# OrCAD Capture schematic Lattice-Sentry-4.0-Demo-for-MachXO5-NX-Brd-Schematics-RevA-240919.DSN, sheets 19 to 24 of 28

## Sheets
19 LCMXO3D BANK2_3_4_5: size B
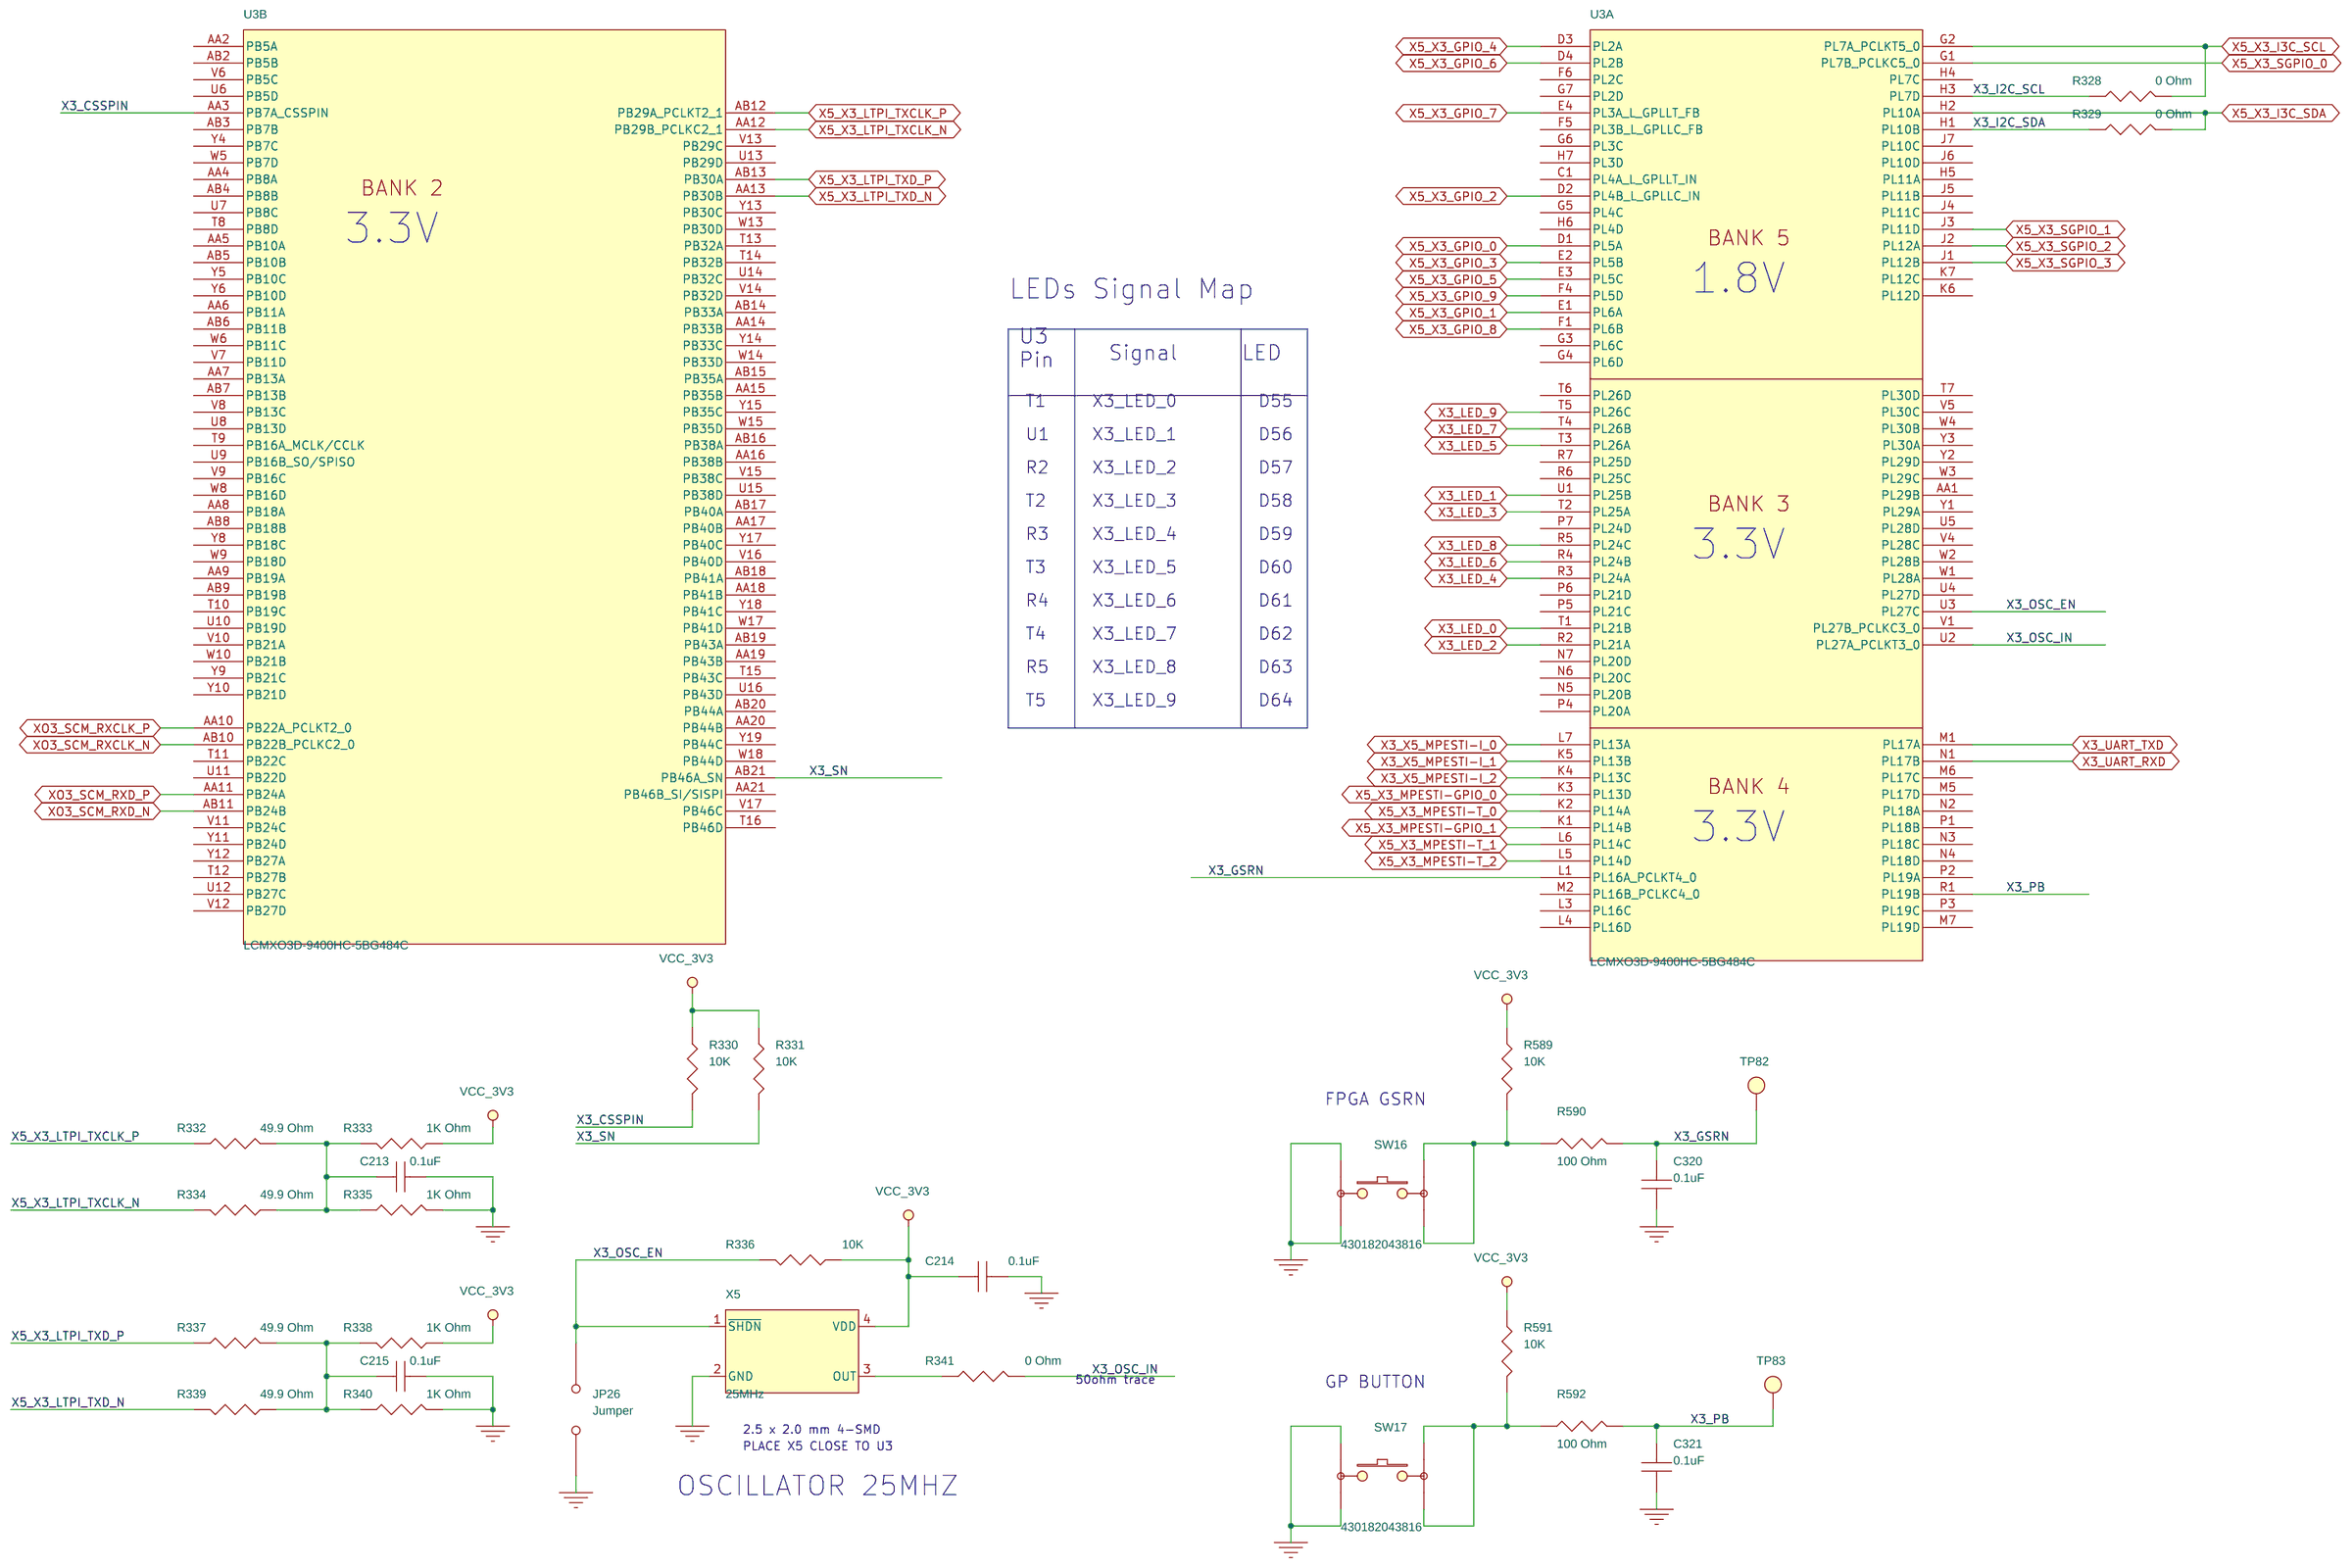
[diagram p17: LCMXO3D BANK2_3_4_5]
20 LCMXO3D POWER: size B
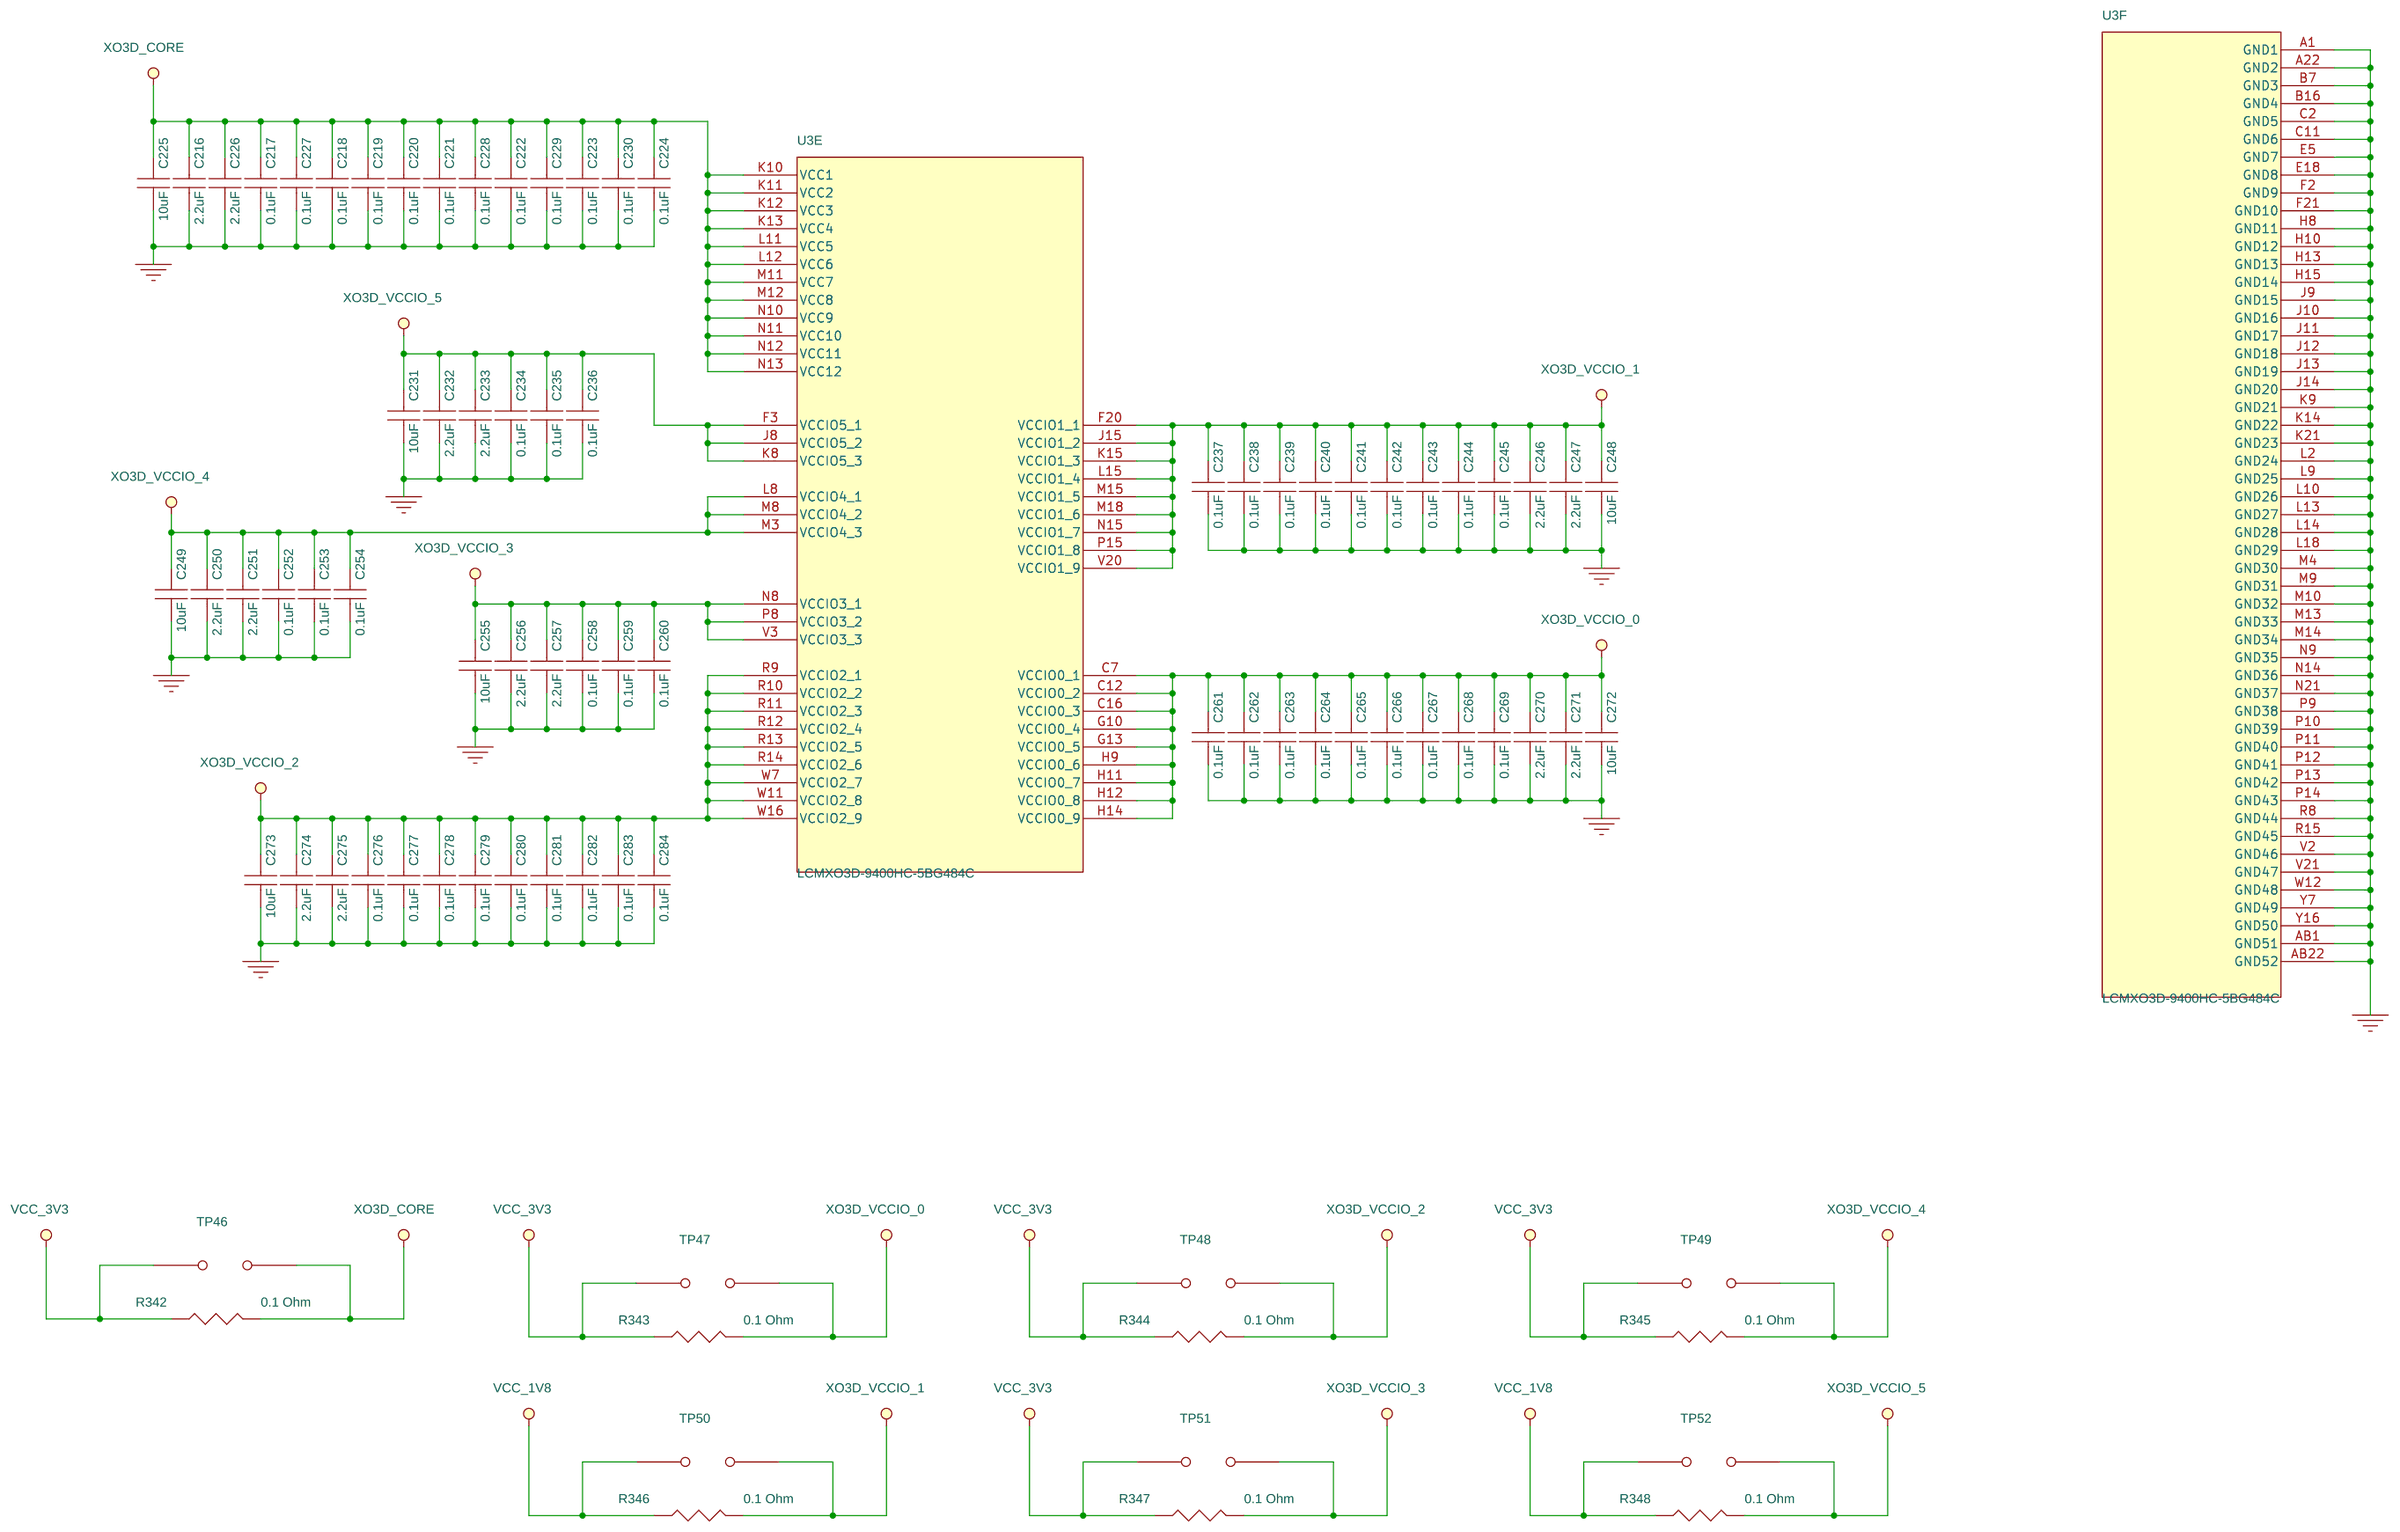
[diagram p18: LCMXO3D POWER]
21 MPESTI: size B
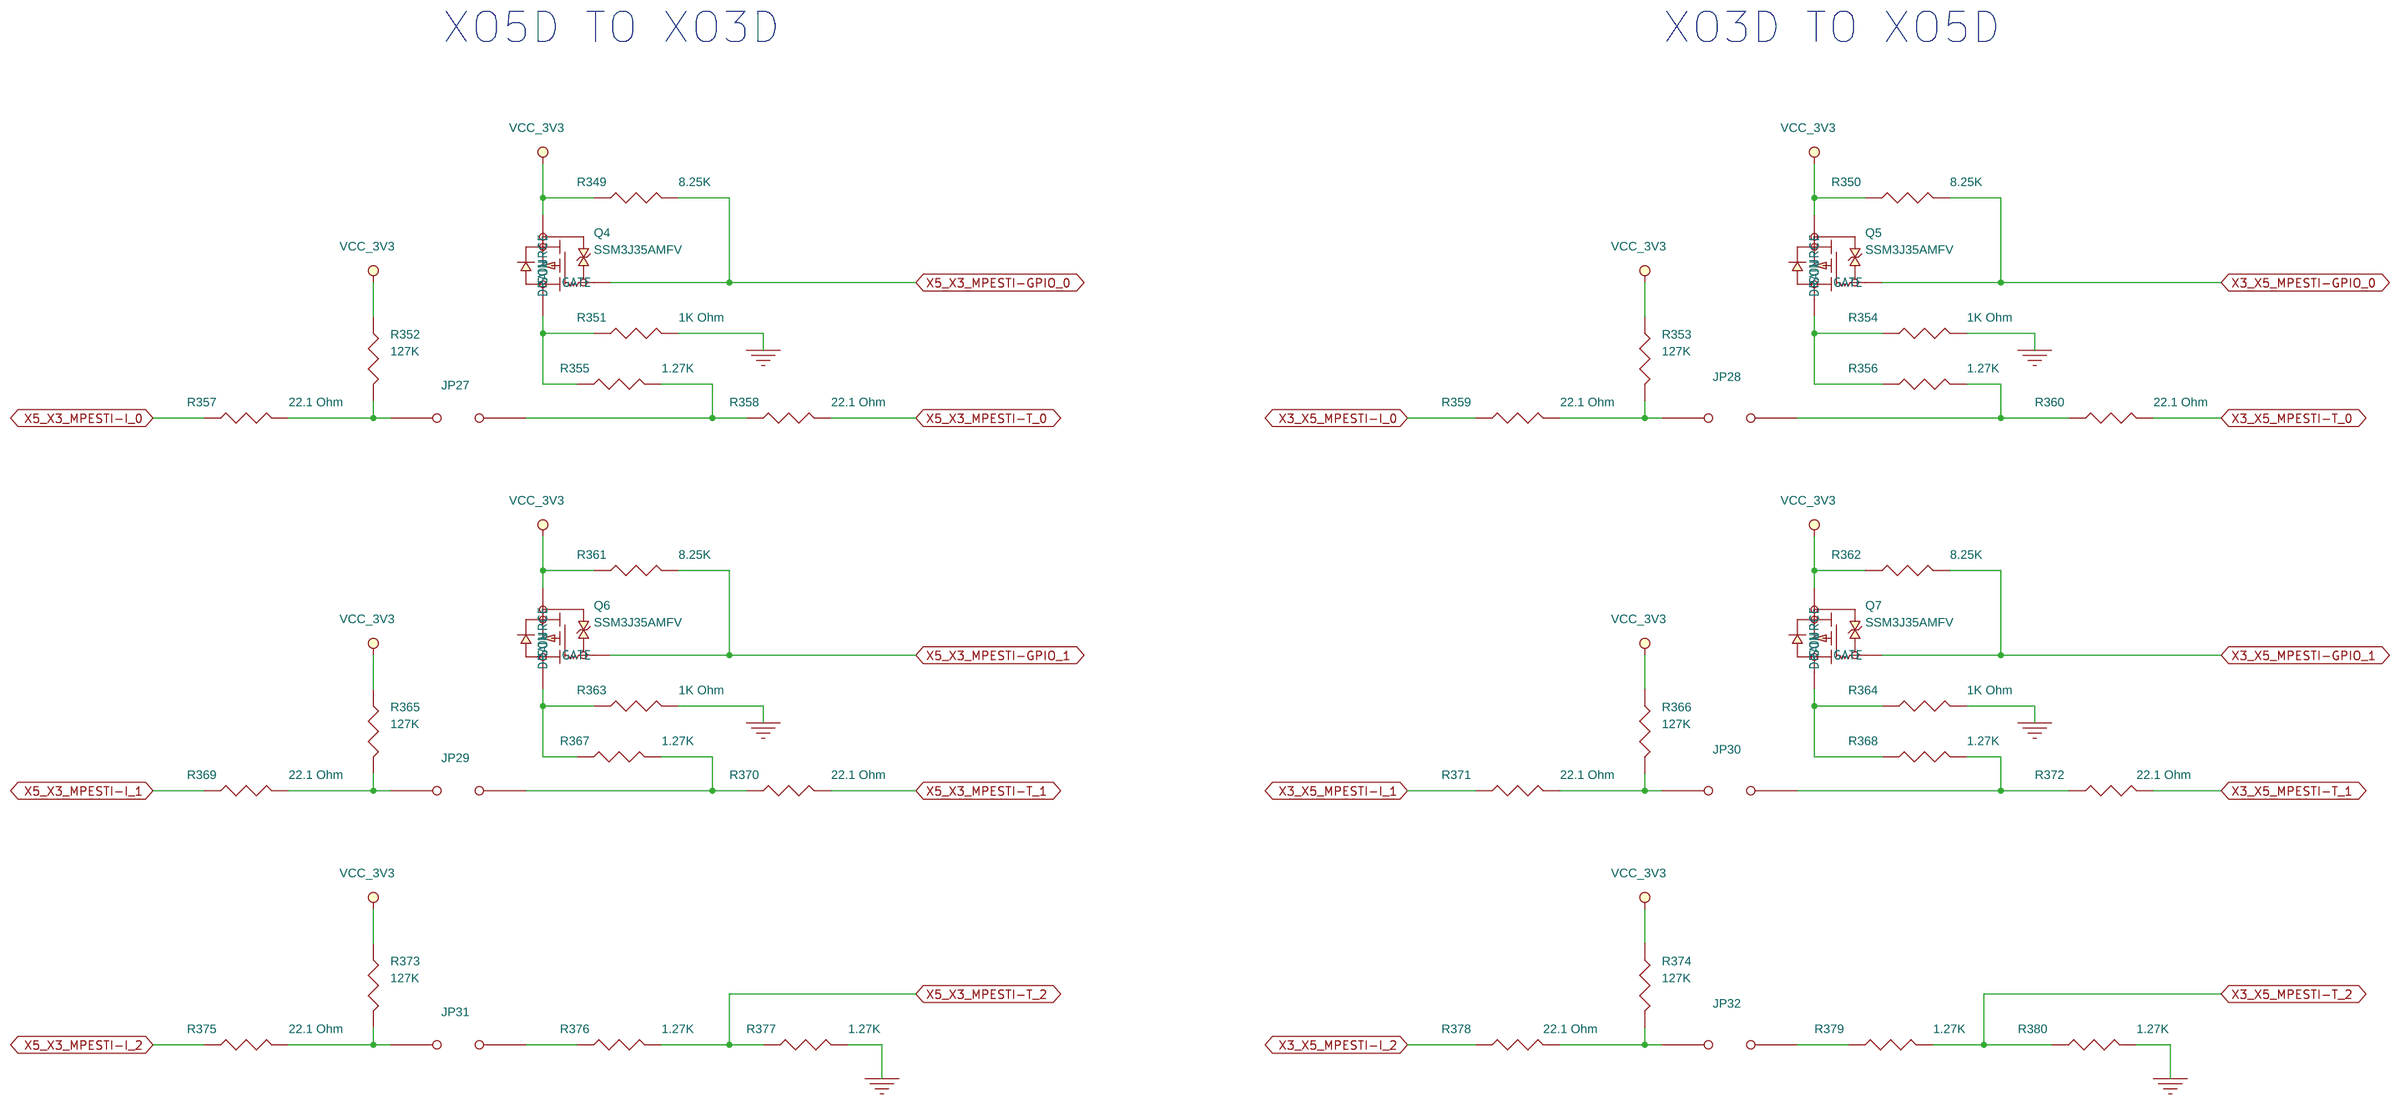
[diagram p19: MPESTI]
22 BMC Flash: size B
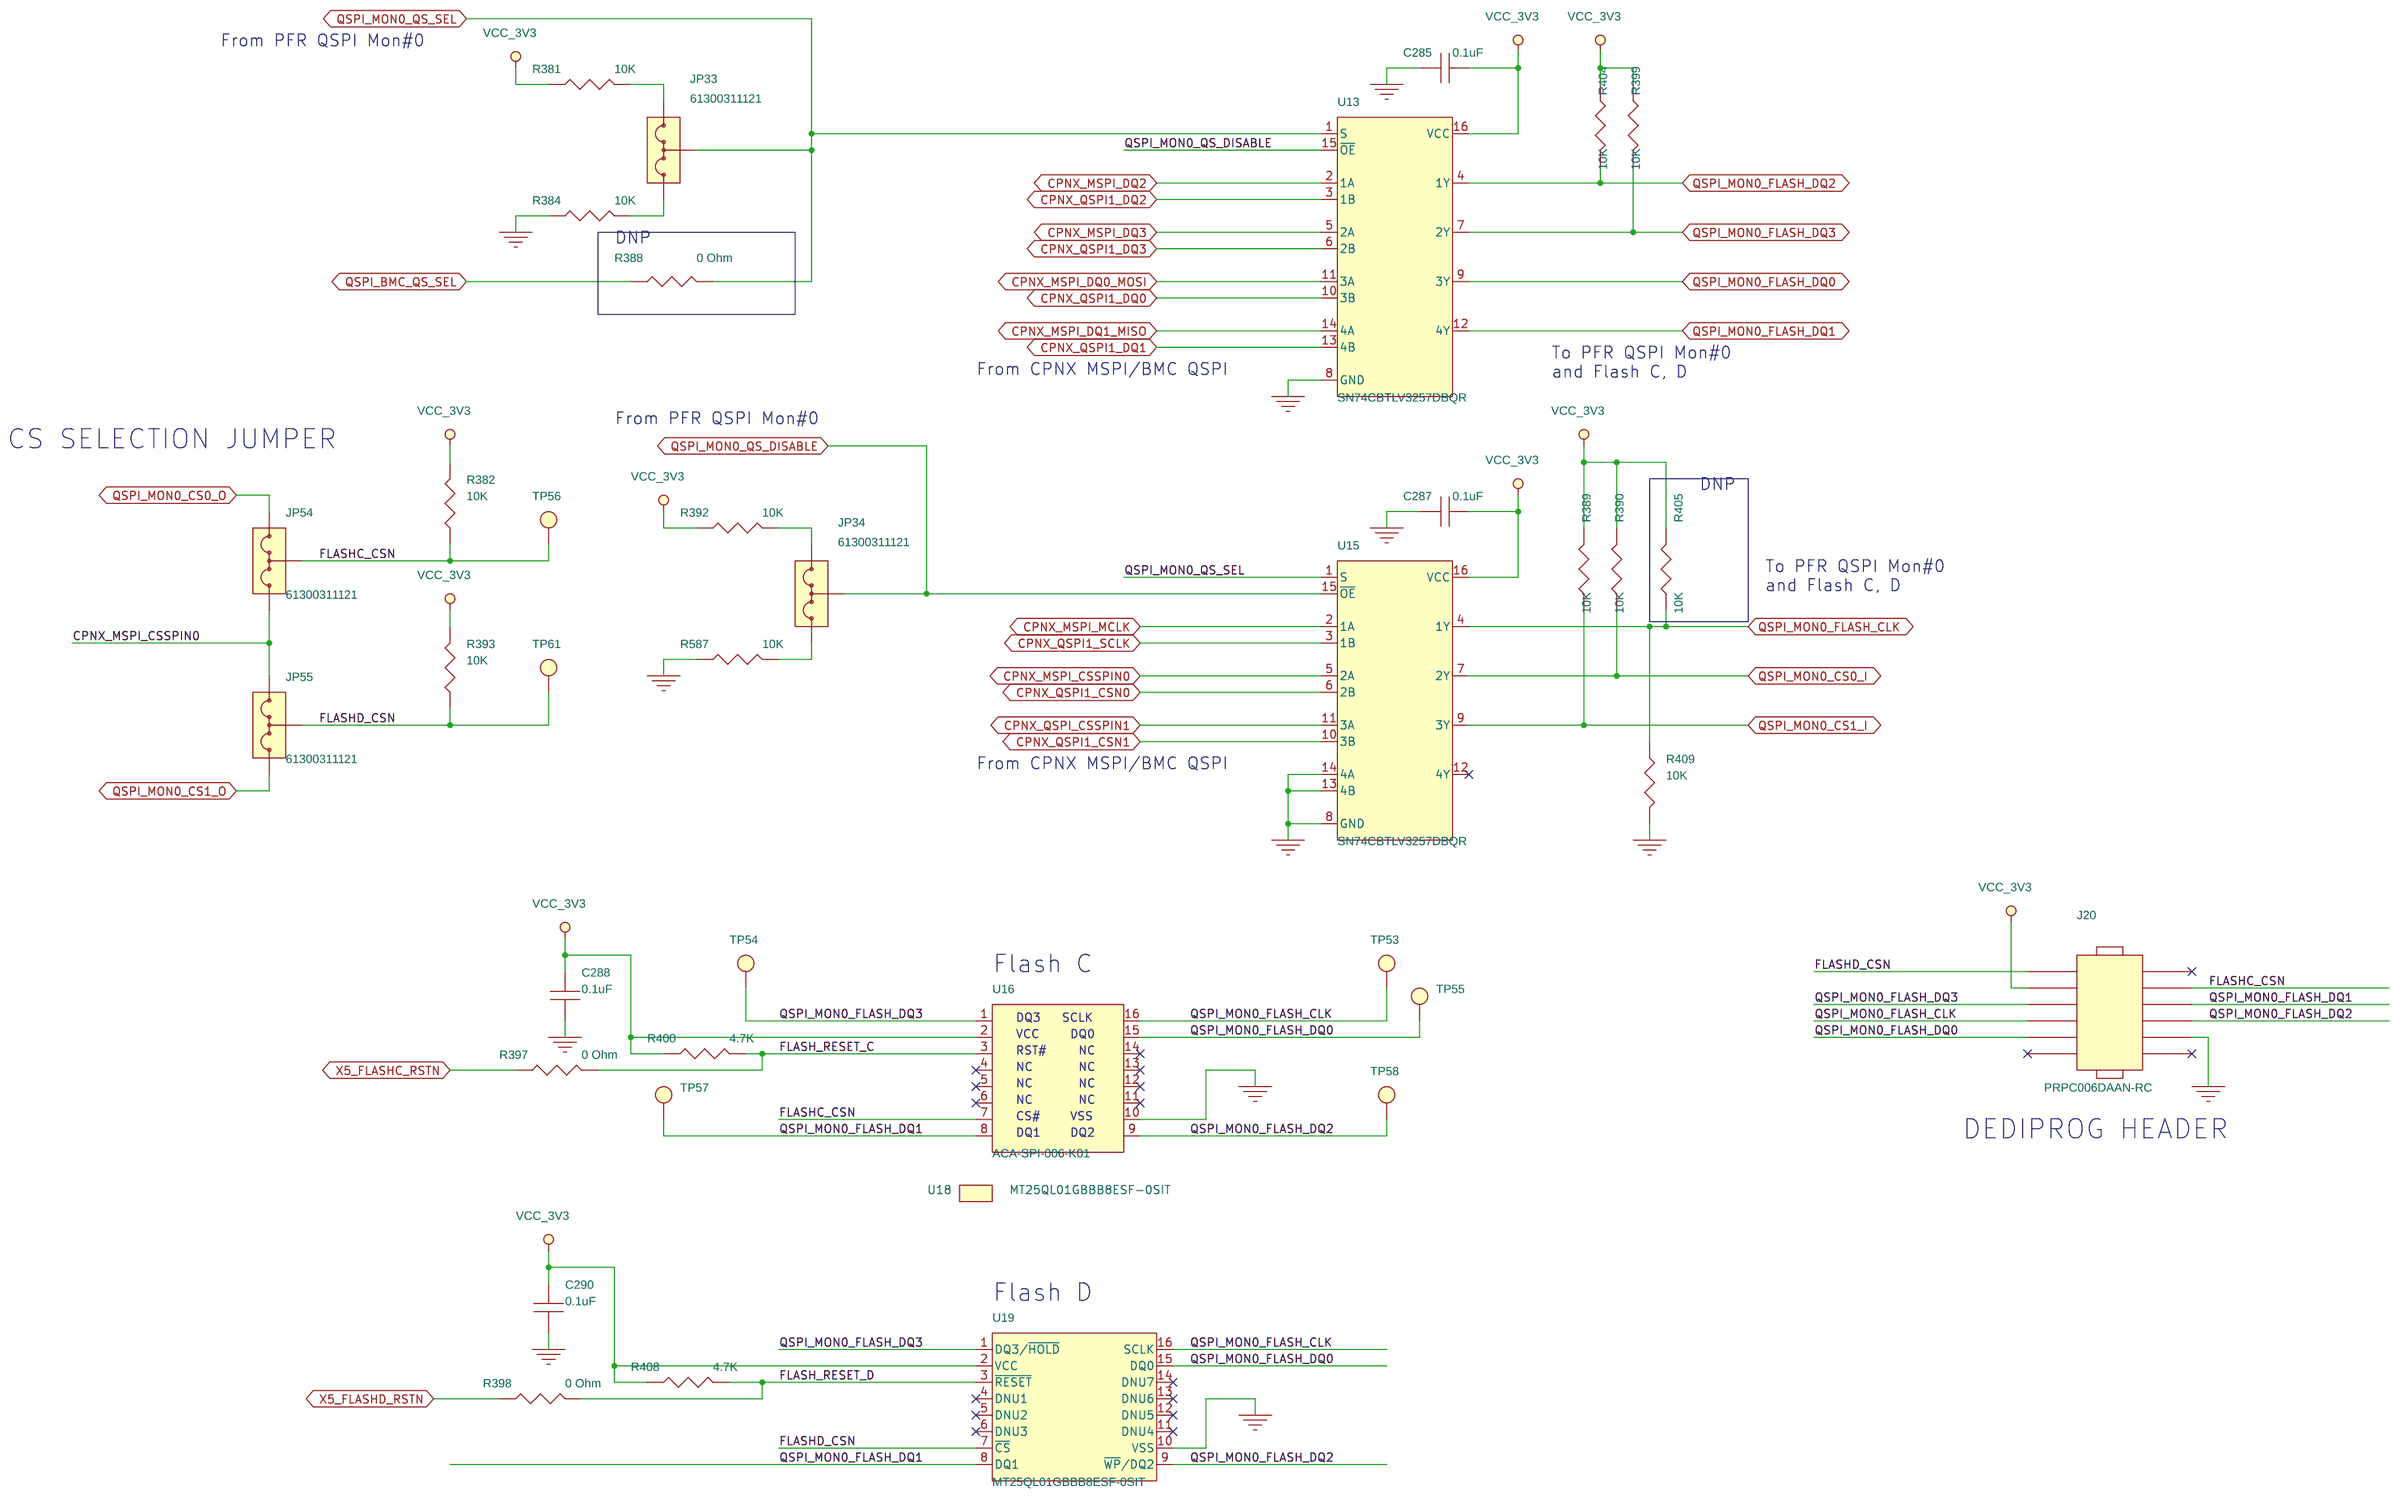
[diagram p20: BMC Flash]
23 PCH Flash: size B
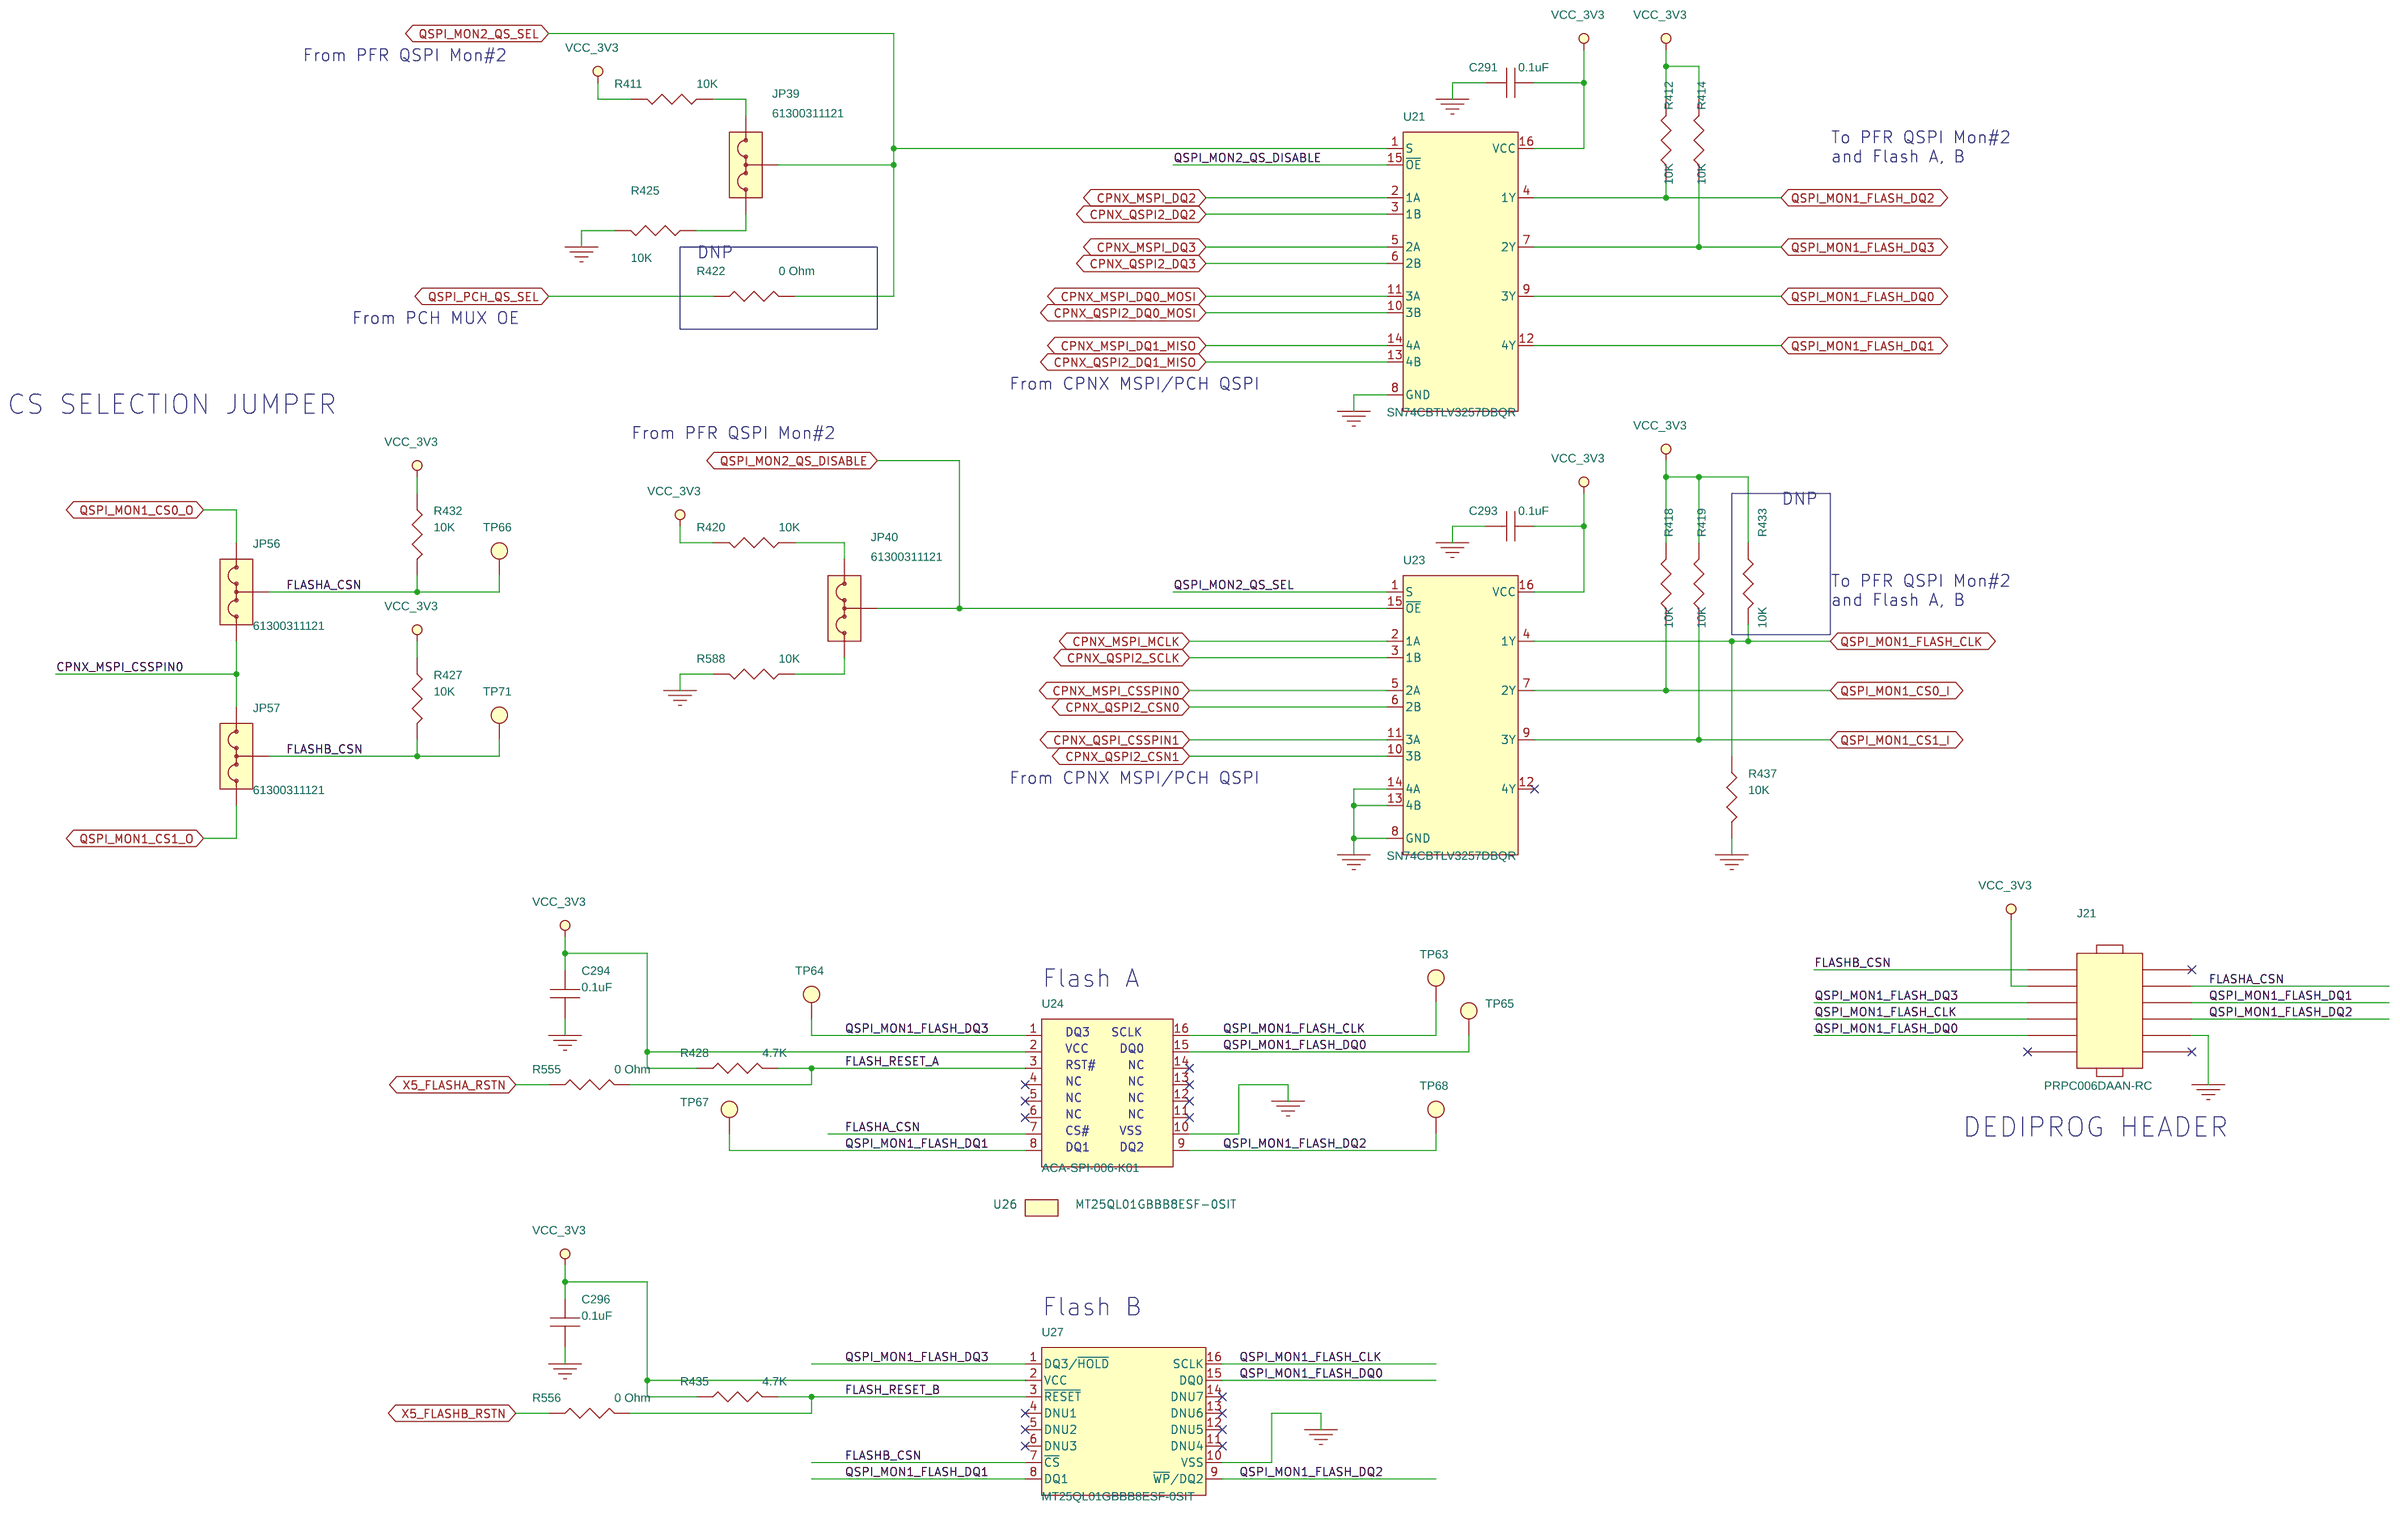
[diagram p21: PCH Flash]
24 JTAG Chain: size B
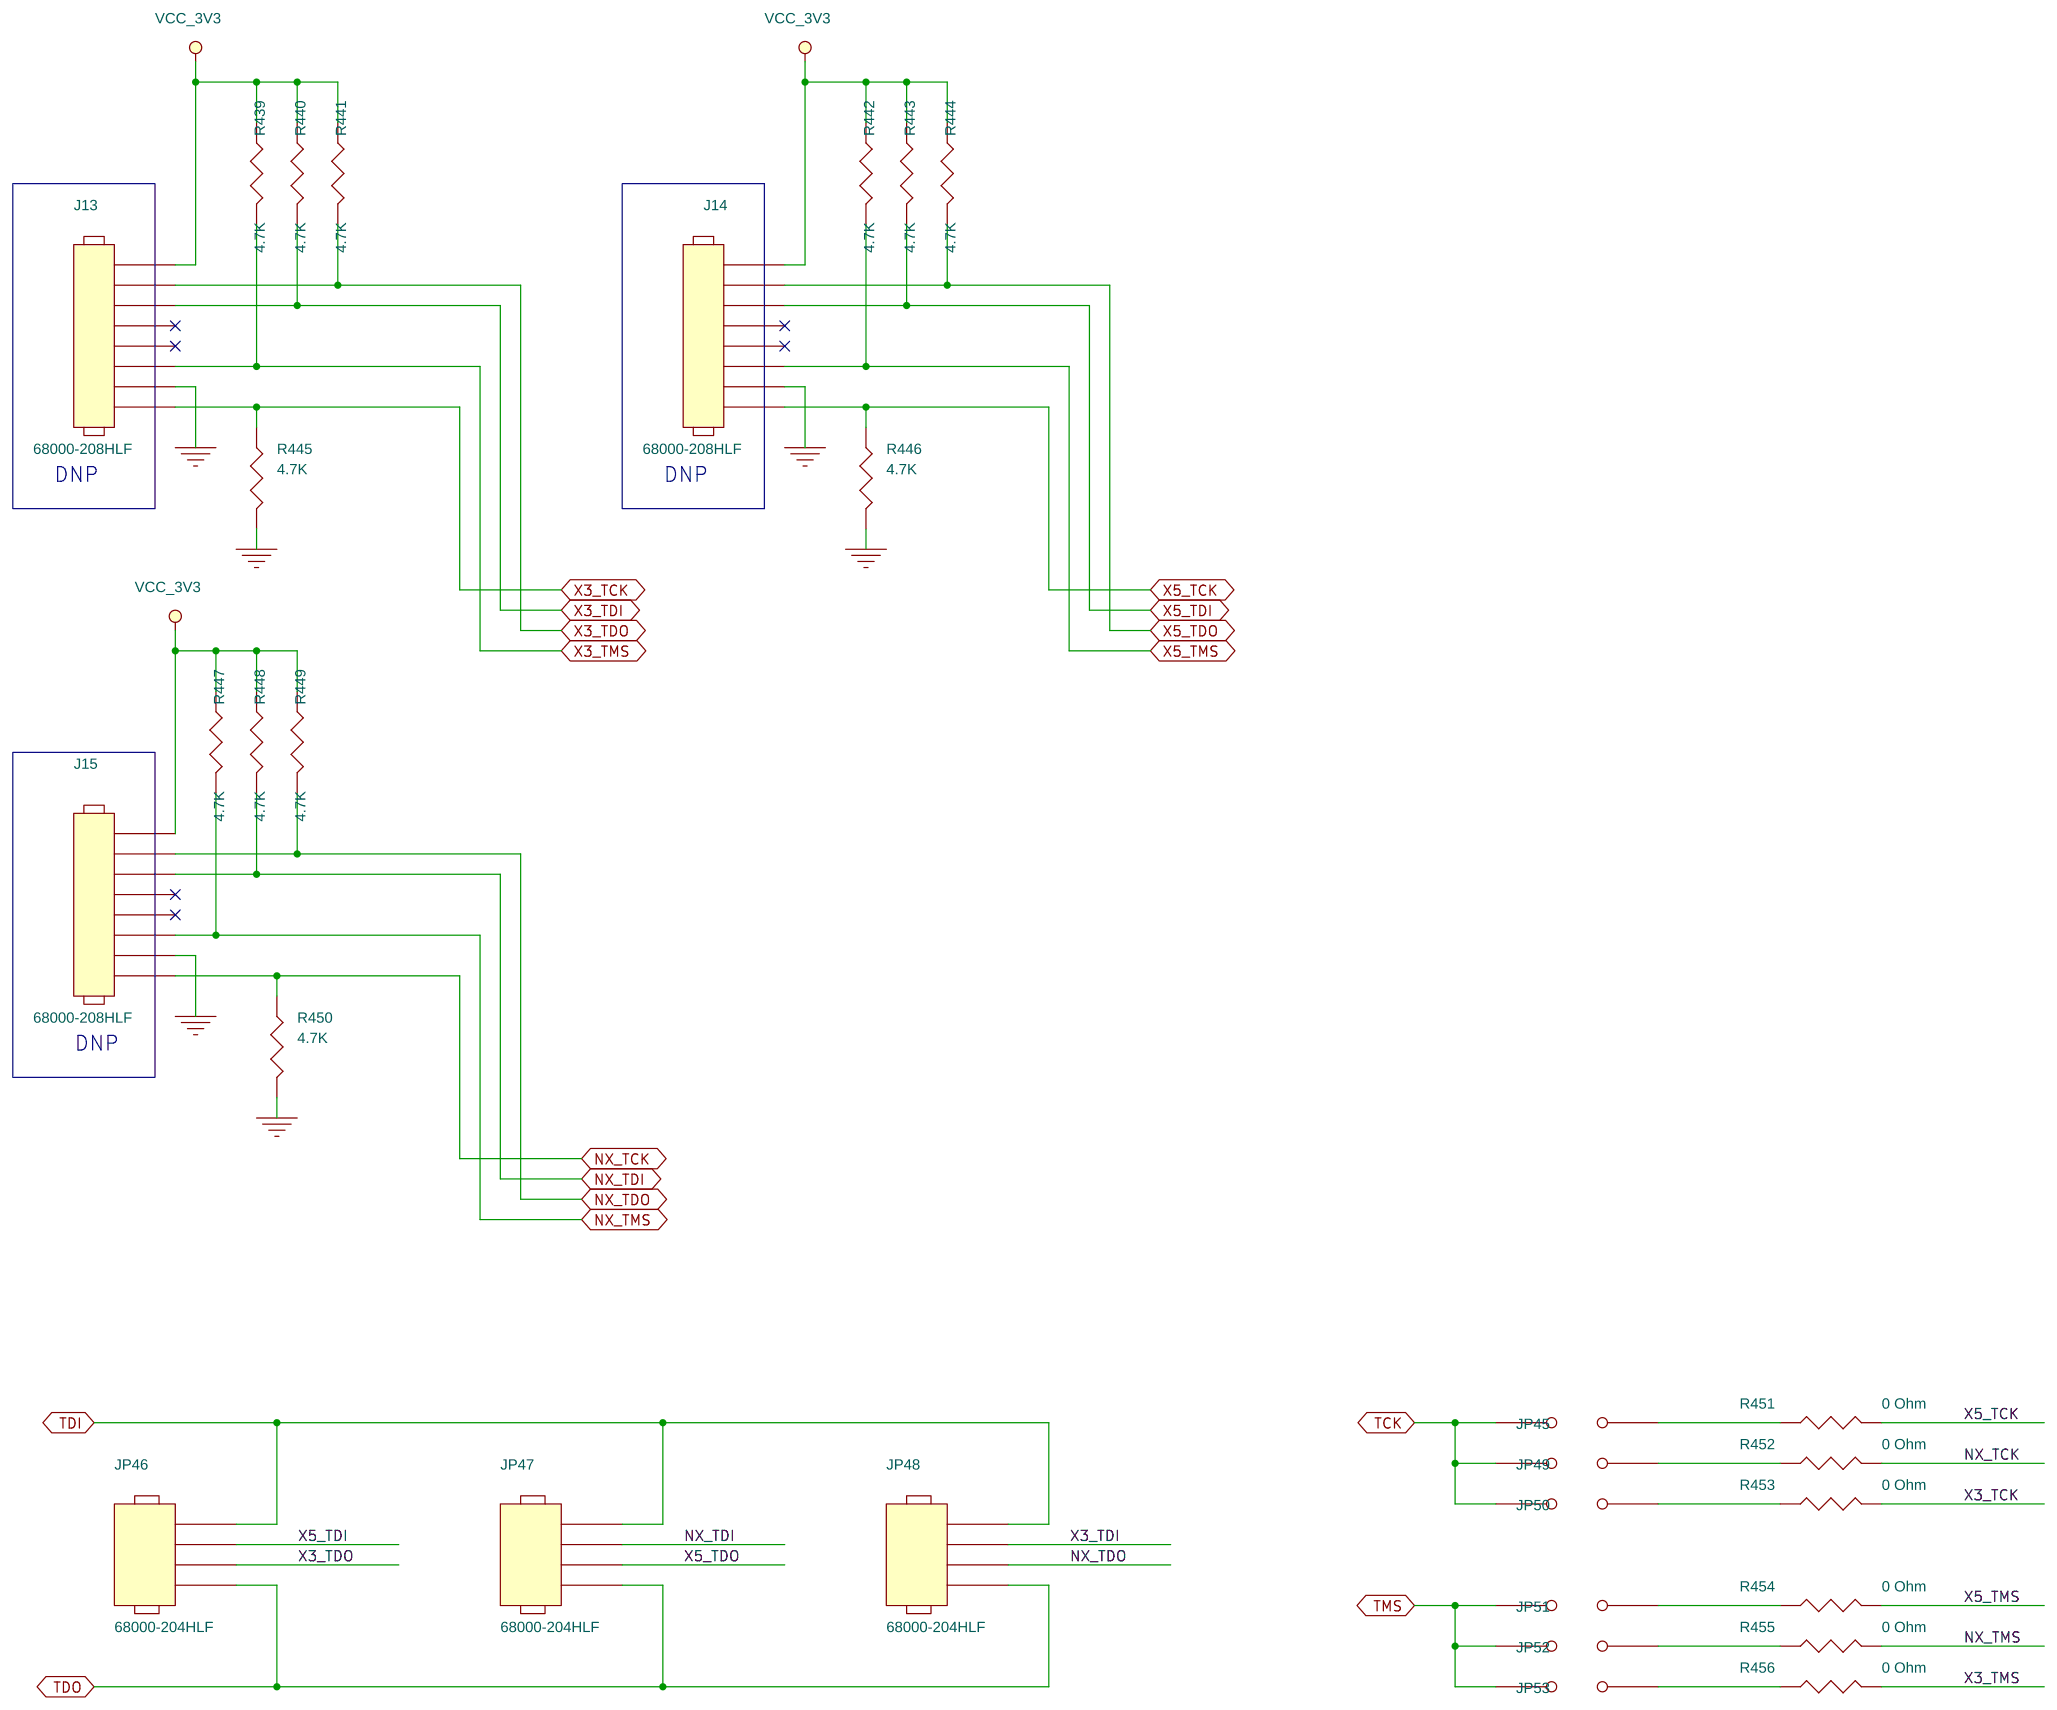
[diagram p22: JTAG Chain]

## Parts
sheet BMC Flash
C285  0.1uF  [C0402-L]
C287  0.1uF  [C0402-L]
C288  0.1uF  [C0402-L]
C290  0.1uF  [C0402-L]
J20  PRPC006DAAN-RC  [CONN_PRPC006DAAN-RC_SUL]
JP33  61300311121  [CONN03_6130_7P62X2P54_WRE]
JP34  61300311121  [CONN03_6130_7P62X2P54_WRE]
JP54  61300311121  [CONN03_6130_7P62X2P54_WRE]
JP55  61300311121  [CONN03_6130_7P62X2P54_WRE]
R381  10K  [R0402-L]
R382  10K  [R0402-L]
R384  10K  [R0402-L]
R388  0 Ohm  [R0402-L]
R389  10K  [R0402-L]
R390  10K  [R0402-L]
R392  10K  [R0402-L]
R393  10K  [R0402-L]
R397  0 Ohm  [R0402-L]
R398  0 Ohm  [R0402-L]
R399  10K  [R0402-L]
R400  4.7K  [R0402-L]
R404  10K  [R0402-L]
R405  10K  [R0402-L]
R408  4.7K  [R0402-L]
R409  10K  [R0402-L]
R587  10K  [R0402-L]
TP53  TP1  [TPd39c60]
TP54  TP1  [TPd39c60]
TP55  TP1  [TPd39c60]
TP56  TP1  [TPd39c60]
TP57  TP1  [TPd39c60]
TP58  TP1  [TPd39c60]
TP61  TP1  [TPd39c60]
U13  SN74CBTLV3257DBQR  [DBQ16]
U15  SN74CBTLV3257DBQR  [DBQ16]
U16  ACA-SPI-006-K01  [ACA-SPI-006-K01_LOTES]
U18  MT25QL01GBBB8ESF-0SIT
U19  MT25QL01GBBB8ESF-0SIT  [SOP2-16_300MIL_SF_MRN]
sheet JTAG Chain
J13  68000-208HLF  [CONN_68000-408HLF_AMP]
J14  68000-208HLF  [CONN_68000-408HLF_AMP]
J15  68000-208HLF  [CONN_68000-408HLF_AMP]
JP45  Jumper  [CONN2_M20-999_1x2_HRW]
JP46  68000-204HLF  [CONN_61300411121_WRE]
JP47  68000-204HLF  [CONN_61300411121_WRE]
JP48  68000-204HLF  [CONN_61300411121_WRE]
JP49  Jumper  [CONN2_M20-999_1x2_HRW]
JP50  Jumper  [CONN2_M20-999_1x2_HRW]
JP51  Jumper  [CONN2_M20-999_1x2_HRW]
JP52  Jumper  [CONN2_M20-999_1x2_HRW]
JP53  Jumper  [CONN2_M20-999_1x2_HRW]
R439  4.7K  [R0402-L]
R440  4.7K  [R0402-L]
R441  4.7K  [R0402-L]
R442  4.7K  [R0402-L]
R443  4.7K  [R0402-L]
R444  4.7K  [R0402-L]
R445  4.7K  [R0402-L]
R446  4.7K  [R0402-L]
R447  4.7K  [R0402-L]
R448  4.7K  [R0402-L]
R449  4.7K  [R0402-L]
R450  4.7K  [R0402-L]
R451  0 Ohm  [R0402-L]
R452  0 Ohm  [R0402-L]
R453  0 Ohm  [R0402-L]
R454  0 Ohm  [R0402-L]
R455  0 Ohm  [R0402-L]
R456  0 Ohm  [R0402-L]
sheet LCMXO3D BANK2_3_4_5
C213  0.1uF  [C0402-L]
C214  0.1uF  [C0402-L]
C215  0.1uF  [C0402-L]
C320  0.1uF  [C0402-L]
C321  0.1uF  [C0402-L]
JP26  Jumper  [CONN2_M20-999_1x2_HRW]
R328  0 Ohm  [R0402-L]
R329  0 Ohm  [R0402-L]
R330  10K  [R0402-L]
R331  10K  [R0402-L]
R332  49.9 Ohm  [R0402-L]
R333  1K Ohm  [R0402-L]
R334  49.9 Ohm  [R0402-L]
R335  1K Ohm  [R0402-L]
R336  10K  [R0402-L]
R337  49.9 Ohm  [R0402-L]
R338  1K Ohm  [R0402-L]
R339  49.9 Ohm  [R0402-L]
R340  1K Ohm  [R0402-L]
R341  0 Ohm  [R0402-L]
R589  10K  [R0402-L]
R590  100 Ohm  [R0402-L]
R591  10K  [R0402-L]
R592  100 Ohm  [R0402-L]
SW16  430182043816  [SOIC_82043816_WRE]
SW17  430182043816  [SOIC_82043816_WRE]
TP82  TP1  [TPd39c60]
TP83  TP1  [TPd39c60]
U3  LCMXO3D-9400HC-5BG484C  [caBGA-080p19x19-484]  (sections A,B,C,D,E,F,G)
X5  25MHz  [ECS-2520MV_ECS]
sheet LCMXO3D POWER
C216  2.2uF  [C0603-L]
C217  0.1uF  [C0402-L]
C218  0.1uF  [C0402-L]
C219  0.1uF  [C0402-L]
C220  0.1uF  [C0402-L]
C221  0.1uF  [C0402-L]
C222  0.1uF  [C0402-L]
C223  0.1uF  [C0402-L]
C224  0.1uF  [C0402-L]
C225  10uF  [C0805-L]
C226  2.2uF  [C0603-L]
C227  0.1uF  [C0402-L]
C228  0.1uF  [C0402-L]
C229  0.1uF  [C0402-L]
C230  0.1uF  [C0402-L]
C231  10uF  [C0805-L]
C232  2.2uF  [C0603-L]
C233  2.2uF  [C0603-L]
C234  0.1uF  [C0402-L]
C235  0.1uF  [C0402-L]
C236  0.1uF  [C0402-L]
C237  0.1uF  [C0402-L]
C238  0.1uF  [C0402-L]
C239  0.1uF  [C0402-L]
C240  0.1uF  [C0402-L]
C241  0.1uF  [C0402-L]
C242  0.1uF  [C0402-L]
C243  0.1uF  [C0402-L]
C244  0.1uF  [C0402-L]
C245  0.1uF  [C0402-L]
C246  2.2uF  [C0603-L]
C247  2.2uF  [C0603-L]
C248  10uF  [C0805-L]
C249  10uF  [C0805-L]
C250  2.2uF  [C0603-L]
C251  2.2uF  [C0603-L]
C252  0.1uF  [C0402-L]
C253  0.1uF  [C0402-L]
C254  0.1uF  [C0402-L]
C255  10uF  [C0805-L]
C256  2.2uF  [C0603-L]
C257  2.2uF  [C0603-L]
C258  0.1uF  [C0402-L]
C259  0.1uF  [C0402-L]
C260  0.1uF  [C0402-L]
C261  0.1uF  [C0402-L]
C262  0.1uF  [C0402-L]
C263  0.1uF  [C0402-L]
C264  0.1uF  [C0402-L]
C265  0.1uF  [C0402-L]
C266  0.1uF  [C0402-L]
C267  0.1uF  [C0402-L]
C268  0.1uF  [C0402-L]
C269  0.1uF  [C0402-L]
C270  2.2uF  [C0603-L]
C271  2.2uF  [C0603-L]
C272  10uF  [C0805-L]
C273  10uF  [C0805-L]
C274  2.2uF  [C0603-L]
C275  2.2uF  [C0603-L]
C276  0.1uF  [C0402-L]
C277  0.1uF  [C0402-L]
C278  0.1uF  [C0402-L]
C279  0.1uF  [C0402-L]
C280  0.1uF  [C0402-L]
C281  0.1uF  [C0402-L]
C282  0.1uF  [C0402-L]
C283  0.1uF  [C0402-L]
C284  0.1uF  [C0402-L]
R342  0.1 Ohm  [R0603-L]
R343  0.1 Ohm  [R0603-L]
R344  0.1 Ohm  [R0603-L]
R345  0.1 Ohm  [R0603-L]
R346  0.1 Ohm  [R0603-L]
R347  0.1 Ohm  [R0603-L]
R348  0.1 Ohm  [R0603-L]
TP46  Jumper  [CONN2_M20-999_1x2_HRW]
TP47  Jumper  [CONN2_M20-999_1x2_HRW]
TP48  Jumper  [CONN2_M20-999_1x2_HRW]
TP49  Jumper  [CONN2_M20-999_1x2_HRW]
TP50  Jumper  [CONN2_M20-999_1x2_HRW]
TP51  Jumper  [CONN2_M20-999_1x2_HRW]
TP52  Jumper  [CONN2_M20-999_1x2_HRW]
sheet MPESTI
JP27  Jumper  [CONN2_M20-999_1x2_HRW]
JP28  Jumper  [CONN2_M20-999_1x2_HRW]
JP29  Jumper  [CONN2_M20-999_1x2_HRW]
JP30  Jumper  [CONN2_M20-999_1x2_HRW]
JP31  Jumper  [CONN2_M20-999_1x2_HRW]
JP32  Jumper  [CONN2_M20-999_1x2_HRW]
Q4  SSM3J35AMFV  [VESM_TOS]
Q5  SSM3J35AMFV  [VESM_TOS]
Q6  SSM3J35AMFV  [VESM_TOS]
Q7  SSM3J35AMFV  [VESM_TOS]
R349  8.25K  [R0402-L]
R350  8.25K  [R0402-L]
R351  1K Ohm  [R0402-L]
R352  127K  [R0402-L]
R353  127K  [R0402-L]
R354  1K Ohm  [R0402-L]
R355  1.27K  [R0402-L]
R356  1.27K  [R0402-L]
R357  22.1 Ohm  [R0402-L]
R358  22.1 Ohm  [R0402-L]
R359  22.1 Ohm  [R0402-L]
R360  22.1 Ohm  [R0402-L]
R361  8.25K  [R0402-L]
R362  8.25K  [R0402-L]
R363  1K Ohm  [R0402-L]
R364  1K Ohm  [R0402-L]
R365  127K  [R0402-L]
R366  127K  [R0402-L]
R367  1.27K  [R0402-L]
R368  1.27K  [R0402-L]
R369  22.1 Ohm  [R0402-L]
R370  22.1 Ohm  [R0402-L]
R371  22.1 Ohm  [R0402-L]
R372  22.1 Ohm  [R0402-L]
R373  127K  [R0402-L]
R374  127K  [R0402-L]
R375  22.1 Ohm  [R0402-L]
R376  1.27K  [R0402-L]
R377  1.27K  [R0402-L]
R378  22.1 Ohm  [R0402-L]
R379  1.27K  [R0402-L]
R380  1.27K  [R0402-L]
sheet PCH Flash
C291  0.1uF  [C0402-L]
C293  0.1uF  [C0402-L]
C294  0.1uF  [C0402-L]
C296  0.1uF  [C0402-L]
J21  PRPC006DAAN-RC  [CONN_PRPC006DAAN-RC_SUL]
JP39  61300311121  [CONN03_6130_7P62X2P54_WRE]
JP40  61300311121  [CONN03_6130_7P62X2P54_WRE]
JP56  61300311121  [CONN03_6130_7P62X2P54_WRE]
JP57  61300311121  [CONN03_6130_7P62X2P54_WRE]
R411  10K  [R0402-L]
R412  10K  [R0402-L]
R414  10K  [R0402-L]
R418  10K  [R0402-L]
R419  10K  [R0402-L]
R420  10K  [R0402-L]
R422  0 Ohm  [R0402-L]
R425  10K  [R0402-L]
R427  10K  [R0402-L]
R428  4.7K  [R0402-L]
R432  10K  [R0402-L]
R433  10K  [R0402-L]
R435  4.7K  [R0402-L]
R437  10K  [R0402-L]
R555  0 Ohm  [R0402-L]
R556  0 Ohm  [R0402-L]
R588  10K  [R0402-L]
TP63  TP1  [TPd39c60]
TP64  TP1  [TPd39c60]
TP65  TP1  [TPd39c60]
TP66  TP1  [TPd39c60]
TP67  TP1  [TPd39c60]
TP68  TP1  [TPd39c60]
TP71  TP1  [TPd39c60]
U21  SN74CBTLV3257DBQR  [DBQ16]
U23  SN74CBTLV3257DBQR  [DBQ16]
U24  ACA-SPI-006-K01  [ACA-SPI-006-K01_LOTES]
U26  MT25QL01GBBB8ESF-0SIT
U27  MT25QL01GBBB8ESF-0SIT  [SOP2-16_300MIL_SF_MRN]

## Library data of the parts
C213-C215 C217-C224 C227-C230 C234-C245 C252-C254 C258-C269 C276-C285 C287 C288 C290 C291 C293 C294 C296 C320 C321 = CAP_NP: 0.1 µF ±10% 50V Ceramic Capacitor X7R 0402 (1005 Metric); Manufacturer: Murata; Manufacturer Part Number: GRM155R71H104KE14J; Part Number: GRM155R71H104KE14J; Part type: Ceramic; Tolerance: 10%; Voltage: 50V; Datasheet: https://search.murata.co.jp/Ceramy/image/img/A01X/G101/ENG/GRM155R71H104KE14-01.pdf
J20 J21 = HEADER_6X2: Connector Header Through Hole 12 position 0.100" (2.54mm); Manufacturer: Sullins; Part Type: Connector; Datasheet: https://drawings-pdf.s3.amazonaws.com/11636.pdf
JP33 JP34 JP39 JP40 JP54-JP57 = JUMP_3: Connector Header Through Hole 3 position 0.100" (2.54mm); Manufacturer: Wurth; Part Type: Connector; Datasheet: https://www.we-online.com/katalog/datasheet/6130xx11121.pdf
R330 R331 R336 R381 R382 R384 R389 R390 R392 R393 R399 R404 R409 R411 R412 R414 R418-R420 R425 R427 R432 R437 R587-R589 R591 = R: 10 kOhms ±1% 0.063W, 1/16W Chip Resistor 0402 (1005 Metric) Thick Film; Manufacturer: Yageo; Manufacturer Part Number: RC0402FR-0710KP; Part Number: RC0402FR-0710KP; Part type: Thick Film; Power: 1/16W; Tolerance: 1%; Datasheet: https://www.yageo.com/upload/media/product/products/datasheet/rchip/PYu-RC_51_RoHS_P_4.pdf
R388 R422 = R: 0 Ohms Jumper Chip Resistor 0402 (1005 Metric) Moisture Resistant Thick Film; Assy: DNL; Manufacturer: Yageo; Manufacturer Part Number: RC0402FR-070RL; Part Number: RC0402FR-070RL; Part type: Thick Film; Datasheet: https://www.yageo.com/upload/media/product/productsearch/datasheet/rchip/PYu-RC_Group_51_RoHS_L_12.pdf
R328 R329 R341 R397 R398 R451-R456 R555 R556 = R: 0 Ohms Jumper Chip Resistor 0402 (1005 Metric) Moisture Resistant Thick Film; Manufacturer: Yageo; Manufacturer Part Number: RC0402FR-070RL; Part Number: RC0402FR-070RL; Part type: Thick Film; Datasheet: https://www.yageo.com/upload/media/product/productsearch/datasheet/rchip/PYu-RC_Group_51_RoHS_L_12.pdf
R400 R408 R428 R435 R439-R450 = R: 4.7 kOhms ±1% 0.063W, 1/16W Chip Resistor 0402 (1005 Metric) Thick Film; Manufacturer: Yageo; Manufacturer Part Number: RC0402FR-074K7P; Part Number: RC0402FR-074K7P; Part type: Thick Film; Power: 1/16W; Tolerance: 1%; Datasheet: https://www.yageo.com/upload/media/product/products/datasheet/rchip/PYu-RC_51_RoHS_P_4.pdf
R405 R433 = R: 10 kOhms ±1% 0.063W, 1/16W Chip Resistor 0402 (1005 Metric) Thick Film; Assy: DNL; Manufacturer: Yageo; Manufacturer Part Number: RC0402FR-0710KP; Part Number: RC0402FR-0710KP; Part type: Thick Film; Power: 1/16W; Tolerance: 1%; Datasheet: https://www.yageo.com/upload/media/product/products/datasheet/rchip/PYu-RC_51_RoHS_P_4.pdf
TP53-TP58 TP61 TP63-TP68 TP71 TP82 TP83 = TP1: Test Point 0.39"; Manufacturer: NA; Part Type: Test Point; Datasheet: NA
U13 U15 U21 U23 = 74XXXX3257: Multiplexer/Demultiplexer 4 x 1:2 16-SSOP; Manufacturer: Texas Instruments; Part Type: MUX; Datasheet: https://www.ti.com/general/docs/suppproductinfo.tsp?distId=10&gotoUrl=https%3A%2F%2Fwww.ti.com%2Flit%2Fgpn%2Fsn74cbtlv3257
U16 U24 = SOIC_SOCKET_16: 16 (2 x 8) Pos SOIC Socket Gold Surface Mount; Manufacturer: Lotes; Datasheet: https://mm.digikey.com/Volume0/opasdata/d220001/medias/docus/5561/ACA-SPI-006-K01%20Drawing.pdf
U18 U26 = BOM-ONLY: FLASH - NOR Memory IC 1Gbit SPI - Quad I/O 133 MHz 16-SO; Manufacturer: Micron; Part Number: MT25QL01GBBB8ESF-0SIT-BOM-ONLY; Part Type: FLASH; Datasheet: https://mm.digikey.com/Volume0/opasdata/d220001/medias/docus/1104/MT25QL01GBBB.pdf
U19 U27 = MT25QXXXX: FLASH - NOR Memory IC 1Gbit SPI - Quad I/O 133 MHz 16-SO; Manufacturer: Micron; Part Type: FLASH; Datasheet: https://mm.digikey.com/Volume0/opasdata/d220001/medias/docus/1104/MT25QL01GBBB.pdf
J13-J15 = HEADER_8: Connector Header Through Hole 8 position 0.100" (2.54mm); Assy: DNL; Manufacturer: Amphenol; Part Type: Connector; Datasheet: https://cdn.amphenol-cs.com/media/wysiwyg/files/drawing/68000.pdf
JP45 JP49-JP53 = JUMPER: Connector Header Through Hole 2 position 0.100" (2.54mm); MANUFACTURER: Sullins; MFR PART NO.: 61300211121; Manufacturer Part Number: PREC002SAAN-RC; PACKAGE: TH; PART DESCRIPTION: CONN HEADER VERT 2POS 2.54MM; Part Number: PREC002SAAN-RC; Datasheet: https://media.digikey.com/PDF/Data%20Sheets/Sullins%20PDFs/z%20RzCzzzSzzN-RC,%20ST,11635-B.pdf
JP46-JP48 = HEADER_4: Connector Header Through Hole 4 position 0.100" (2.54mm); Manufacturer: Amphenol; Part Type: Connector; Datasheet: https://cdn.amphenol-cs.com/media/wysiwyg/files/drawing/68000.pdf
JP26-JP32 TP46-TP52 = JUMPER: Connector Header Through Hole 2 position 0.100" (2.54mm); Manufacturer: Sullins; Manufacturer Part Number: PREC002SAAN-RC; Part Number: PREC002SAAN-RC; Datasheet: https://media.digikey.com/PDF/Data%20Sheets/Sullins%20PDFs/z%20RzCzzzSzzN-RC,%20ST,11635-B.pdf
R332 R334 R337 R339 = R: 49.9 Ohms ±1% 0.063W, 1/16W Chip Resistor 0402 (1005 Metric) Moisture Resistant Thick Film; Manufacturer: Yageo; Manufacturer Part Number: RC0402FR-0749R9L; Part Number: RC0402FR-0749R9L; Part type: Thick Film; Power: 1/16W; Tolerance: 1%; Datasheet: https://www.yageo.com/upload/media/product/app/datasheet/rchip/pyu-rc_group_51_rohs_l.pdf
R333 R335 R338 R340 R351 R354 R363 R364 = R: 1 kOhms ±1% 0.063W, 1/16W Chip Resistor 0402 (1005 Metric) Thick Film; Manufacturer: Yageo; Manufacturer Part Number: RC0402FR-71K2P / RC0402FR-0733R2P; Part Number: RC0402FR-071KP / RC0402FR-0733R2P / RC0402FR-0733R2P; Part type: Thick Film; Power: 1/16W; Tolerance: 1%; Datasheet: https://www.yageo.com/upload/media/product/products/datasheet/rchip/PYu-RC_51_RoHS_P_4.pdf
R590 R592 = R: 100 Ohms ±1% 0.063W, 1/16W Chip Resistor 0402 (1005 Metric) Thick Film; Manufacturer: Yageo; Manufacturer Part Number: RC0402FR-07100KP; Part Number: RC0402FR-07100KP; Part type: Thick Film; Power: 1/16W; Tolerance: 1%; Datasheet: https://www.yageo.com/upload/media/product/productsearch/datasheet/rchip/PYu-RC_Group_51_RoHS_L_12.pdf
SW16 SW17 = SW_PB-SPST-2: Tactile Switch SPST-NO Top Actuated Surface Mount; Manufacturer: Wurth; Datasheet: https://www.we-online.com/katalog/datasheet/4301x2xxx8x6.pdf
U3 = LCMXO3D-9400-BG484: FPGA - Field Programmable Gate Array Lattice MachXO3D; 9400LUTs 2.5V/3.3V; ID: 3; Manufacturer: Lattice Semiconductor; Part Type: FPGA; Datasheet: https://www.latticesemi.com/-/media/LatticeSemi/Documents/DataSheets/MachXO23/FPGA-DS-02026-0-90-MachXO3D-Device-Family.ashx?document_id=52590
X5 = OSC4PIN_SM: 25 MHz XO (Standard) HCMOS Oscillator 1.6V ~ 3.6V Enable/Disable 4-SMD, No Lead; Manufacturer: ECS; Manufacturer Part Number: ECS-2520MV-250-CM-TR; Part Number: ECS-2520MV-250-CM-TR; Part Type: Oscillator; Datasheet: https://ecsxtal.com/store/pdf/ECS-3225MV.pdf
C216 C226 C232 C233 C246 C247 C250 C251 C256 C257 C270 C271 C274 C275 = CAP_NP: 2.2 µF ±10% 25V Ceramic Capacitor X5R 0603 (1608 Metric); Manufacturer: Murata; Manufacturer Part Number: GRM188R61E225KA12J; Part Number: GRM188R61E225KA12J; Part type: Ceramic; Tolerance: 10%; Voltage: 25V; Datasheet: https://search.murata.co.jp/Ceramy/image/img/A01X/G101/ENG/GRM188R61E225KA12-01.pdf
C225 C231 C248 C249 C255 C272 C273 = CAP_NP: 10 µF ±10% 25V Ceramic Capacitor X5R 0805 (2012 Metric); Manufacturer: Murata; Manufacturer Part Number: GRM21BR61E106KA73K; Part Number: GRM21BR61E106KA73K; Part type: Ceramic; Tolerance: 10%; Voltage: 25V; Datasheet: https://search.murata.co.jp/Ceramy/image/img/A01X/G101/ENG/GRM21BR61E106KA73-01.pdf
R342-R348 = R: 100 mOhms ±1% 0.2W, 1/5W Chip Resistor 0603 (1608 Metric) Current Sense Metal Film; Manufacturer: Ohmite; Manufacturer Part Number: KDV06FR100ET; Part Number: KDV06FR100ET; Part type: Metal Film; Tolerance: 1%; Datasheet: https://www.ohmite.com/assets/docs/res_kdv.pdf?r=false
Q4-Q7 = SSM3J35AMFV_0: P-Channel 20 V 250mA (Ta) 150mW (Ta) Surface Mount VESM; Manufacturer: Toshiba Semiconductor; Part Type: MOSFET P-CH; Datasheet: https://mm.digikey.com/Volume0/opasdata/d220001/medias/docus/754/SSM3J35AMFV.pdf
R349 R350 R361 R362 = R: 8.25 kOhms ±1% 0.063W, 1/16W Chip Resistor 0402 (1005 Metric) Moisture Resistant Thick Film; Manufacturer: Yageo; Manufacturer Part Number: RC0402FR-078K25L; Part Number: RC0402FR-078K25L; Part type: Thick Film; Power: 1/16W; Tolerance: 1%; Datasheet: https://www.yageo.com/upload/media/product/app/datasheet/rchip/pyu-rc_group_51_rohs_l.pdf
R352 R353 R365 R366 R373 R374 = R: 127 kOhms ±1% 0.063W, 1/16W Chip Resistor 0402 (1005 Metric) Moisture Resistant Thick Film; Manufacturer: Yageo; Manufacturer Part Number: RC0402FR-07127KL; Part Number: RC0402FR-07127KL; Part type: Thick Film; Power: 1/16W; Tolerance: 1%; Datasheet: https://www.yageo.com/upload/media/product/app/datasheet/rchip/pyu-rc_group_51_rohs_l.pdf
R355 R356 R367 R368 R376 R377 R379 R380 = R: 1.27 kOhms ±1% 0.063W, 1/16W Chip Resistor 0402 (1005 Metric) Moisture Resistant Thick Film; Manufacturer: Yageo; Manufacturer Part Number: RC0402FR-071K27L; Part Number: RC0402FR-071K27L; Part type: Thick Film; Power: 1/16W; Tolerance: 1%; Datasheet: https://www.yageo.com/upload/media/product/app/datasheet/rchip/pyu-rc_group_51_rohs_l.pdf
R357-R360 R369-R372 R375 R378 = R: 22.1 Ohms ±1% 0.063W, 1/16W Chip Resistor 0402 (1005 Metric) Moisture Resistant Thick Film; Manufacturer: Yageo; Manufacturer Part Number: RC0402FR-0722R1L; Part Number: RC0402FR-0722R1L; Part type: Thick Film; Power: 1/16W; Tolerance: 1%; Datasheet: https://www.yageo.com/upload/media/product/app/datasheet/rchip/pyu-rc_group_51_rohs_l.pdf

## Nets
GND: C213.2 C214.2 C215.2 C216.2 C217.2 C218.2 C219.2 C220.2 C221.2 C222.2 C223.2 C224.2 C225.2 C226.2 C227.2 C228.2 C229.2 C230.2 C231.2 C232.2 C233.2 C234.2 C235.2 C236.2 C237.2 C238.2 C239.2 C240.2 C241.2 C242.2 C243.2 C244.2 C245.2 C246.2 C247.2 C248.2 C249.2 C250.2 C251.2 C252.2 C253.2 C254.2 C255.2 C256.2 C257.2 C258.2 C259.2 C260.2 C261.2 C262.2 C263.2 C264.2 C265.2 C266.2 C267.2 C268.2 C269.2 C270.2 C271.2 C272.2 C273.2 C274.2 C275.2 C276.2 C277.2 C278.2 C279.2 C280.2 C281.2 C282.2 C283.2 C284.2 C285.2 C287.2 C288.2 C290.2 C291.2 C293.2 C294.2 C296.2 C320.2 C321.2 J13.7 J14.7 J15.7 J20.9 J21.9 JP26.1 R335.2 R340.2 R351.2 R354.2 R363.2 R364.2 R377.2 R380.2 R384.2 R409.2 R425.2 R437.2 R445.2 R446.2 R450.2 R587.2 R588.2 SW16.1 SW16.3 SW17.1 SW17.3 U3.A1(GND1) U3.A22(GND2) U3.AB1(GND51) U3.AB22(GND52) U3.B7(GND3) U3.B16(GND4) U3.C2(GND5) U3.C11(GND6) U3.E5(GND7) U3.E18(GND8) U3.F2(GND9) U3.F21(GND10) U3.H8(GND11) U3.H10(GND12) U3.H13(GND13) U3.H15(GND14) U3.J9(GND15) U3.J10(GND16) U3.J11(GND17) U3.J12(GND18) U3.J13(GND19) U3.J14(GND20) U3.K9(GND21) U3.K14(GND22) U3.K21(GND23) U3.L2(GND24) U3.L9(GND25) U3.L10(GND26) U3.L13(GND27) U3.L14(GND28) U3.L18(GND29) U3.M4(GND30) U3.M9(GND31) U3.M10(GND32) U3.M13(GND33) U3.M14(GND34) U3.N9(GND35) U3.N14(GND36) U3.N21(GND37) U3.P9(GND38) U3.P10(GND39) U3.P11(GND40) U3.P12(GND41) U3.P13(GND42) U3.P14(GND43) U3.R8(GND44) U3.R15(GND45) U3.V2(GND46) U3.V21(GND47) U3.W12(GND48) U3.Y7(GND49) U3.Y16(GND50) U13.8(GND) U15.8(GND) U15.13(4B) U15.14(4A) U16.10 U19.10(VSS) U21.8(GND) U23.8(GND) U23.13(4B) U23.14(4A) U24.10 U27.10(VSS) X5.2(GND) ; also on sheet 3 4 5 6 7 8 9 10 11 12 13 14 15 16 17 18 25 26 27 28
VCC_1V8: R346.1 R348.1 TP50.2 TP52.2 ; also on sheet 6 8 9 11 15 16 18 26 27 28
VCC_3V3: C214.1 C285.1 C287.1 C288.1 C290.1 C291.1 C293.1 C294.1 C296.1 J13.1 J14.1 J15.1 J20.4 J21.4 Q4.S(SOURCE) Q5.S(SOURCE) Q6.S(SOURCE) Q7.S(SOURCE) R330.1 R331.1 R333.1 R336.1 R338.1 R342.1 R343.1 R344.1 R345.1 R347.1 R349.1 R350.1 R352.1 R353.1 R361.1 R362.1 R365.1 R366.1 R373.1 R374.1 R381.2 R382.1 R389.1 R390.1 R392.1 R393.1 R399.1 R400.1 R404.1 R405.2 R408.1 R411.1 R412.1 R414.1 R418.1 R419.1 R420.1 R427.1 R428.1 R432.1 R433.1 R435.1 R439.1 R440.1 R441.1 R442.1 R443.1 R444.1 R447.1 R448.1 R449.1 R589.1 R591.1 TP46.2 TP47.2 TP48.2 TP49.2 TP51.2 U13.16(VCC) U15.16(VCC) U16.2 U19.2(VCC) U21.16(VCC) U23.16(VCC) U24.2 U27.2(VCC) X5.4(VDD) ; also on sheet 3 4 5 6 7 9 10 11 12 13 14 16 17 25 26 28
CPNX_MSPI_CSSPIN0: JP54.3 JP55.3 JP56.3 JP57.3 U15.5(2A) U23.5(2A) ; also on sheet 12
CPNX_MSPI_DQ0_MOSI: U13.11(3A) U21.11(3A) ; also on sheet 12
CPNX_MSPI_DQ1_MISO: U13.14(4A) U21.14(4A) ; also on sheet 12
CPNX_MSPI_DQ2: U13.2(1A) U21.2(1A) ; also on sheet 12
CPNX_MSPI_DQ3: U13.5(2A) U21.5(2A) ; also on sheet 12
CPNX_MSPI_MCLK: U15.2(1A) U23.2(1A) ; also on sheet 12
CPNX_QSPI1_CSN0: U15.6(2B) ; also on sheet 11
CPNX_QSPI1_CSN1: U15.10(3B) ; also on sheet 11
CPNX_QSPI1_DQ0: U13.10(3B) ; also on sheet 11
CPNX_QSPI1_DQ1: U13.13(4B) ; also on sheet 11
CPNX_QSPI1_DQ2: U13.3(1B) ; also on sheet 11
CPNX_QSPI1_DQ3: U13.6(2B) ; also on sheet 11
CPNX_QSPI1_SCLK: U15.3(1B) ; also on sheet 11
CPNX_QSPI2_CSN0: U23.6(2B) ; also on sheet 14
CPNX_QSPI2_CSN1: U23.10(3B) ; also on sheet 14
CPNX_QSPI2_DQ0_MOSI: U21.10(3B) ; also on sheet 14
CPNX_QSPI2_DQ1_MISO: U21.13(4B) ; also on sheet 14
CPNX_QSPI2_DQ2: U21.3(1B) ; also on sheet 14
CPNX_QSPI2_DQ3: U21.6(2B) ; also on sheet 14
CPNX_QSPI2_SCLK: U23.3(1B) ; also on sheet 14
CPNX_QSPI_CSSPIN1: U15.11(3A) U23.11(3A) ; also on sheet 12
FLASH_RESET_A: R428.2 R555.2 U24.3
FLASH_RESET_B: R435.2 R556.2 U27.3(~{RESET})
FLASH_RESET_C: R397.2 R400.2 U16.3
FLASH_RESET_D: R398.2 R408.2 U19.3(~{RESET})
FLASHA_CSN: J21.3 JP56.2 R432.2 TP66.1 U24.7
FLASHB_CSN: J21.2 JP57.2 R427.2 TP71.1 U27.7(~{CS})
FLASHC_CSN: J20.3 JP54.2 R382.2 TP56.1 U16.7
FLASHD_CSN: J20.2 JP55.2 R393.2 TP61.1 U19.7(~{CS})
NX_TCK: J15.8 R450.1 R452.2 ; also on sheet 11
NX_TDI: J15.3 JP47.2 R448.2 ; also on sheet 11
NX_TDO: J15.2 JP48.3 R449.2 ; also on sheet 11
NX_TMS: J15.6 R447.2 R455.2 ; also on sheet 11
QSPI_BMC_QS_SEL: R388.1 ; also on sheet 12
QSPI_MON0_CS0_I: R390.2 U15.7(2Y) ; also on sheet 4
QSPI_MON0_CS0_O: JP54.1 ; also on sheet 4
QSPI_MON0_CS1_I: R389.2 U15.9(3Y) ; also on sheet 4
QSPI_MON0_CS1_O: JP55.1 ; also on sheet 4
QSPI_MON0_FLASH_CLK: J20.8 R405.1 R409.1 TP53.1 U15.4(1Y) U16.16 U19.16(SCLK) ; also on sheet 4
QSPI_MON0_FLASH_DQ0: J20.10 TP55.1 U13.9(3Y) U16.15 U19.15(DQ0) ; also on sheet 4
QSPI_MON0_FLASH_DQ1: J20.5 TP57.1 U13.12(4Y) U16.8 U19.8(DQ1) ; also on sheet 4
QSPI_MON0_FLASH_DQ2: J20.7 R404.2 TP58.1 U13.4(1Y) U16.9 U19.9(~{WP}/DQ2) ; also on sheet 4
QSPI_MON0_FLASH_DQ3: J20.6 R399.2 TP54.1 U13.7(2Y) U16.1 U19.1(DQ3/~{HOLD}) ; also on sheet 4
QSPI_MON0_QS_DISABLE: JP34.2 U13.15(~{OE}) U15.15(~{OE}) ; also on sheet 4
QSPI_MON0_QS_SEL: JP33.2 R388.2 U13.1(S) U15.1(S) ; also on sheet 4
QSPI_MON1_CS0_I: R418.2 U23.7(2Y) ; also on sheet 7
QSPI_MON1_CS0_O: JP56.1 ; also on sheet 7
QSPI_MON1_CS1_I: R419.2 U23.9(3Y) ; also on sheet 7
QSPI_MON1_CS1_O: JP57.1 ; also on sheet 7
QSPI_MON1_FLASH_CLK: J21.8 R433.2 R437.1 TP63.1 U23.4(1Y) U24.16 U27.16(SCLK) ; also on sheet 7
QSPI_MON1_FLASH_DQ0: J21.10 TP65.1 U21.9(3Y) U24.15 U27.15(DQ0) ; also on sheet 7
QSPI_MON1_FLASH_DQ1: J21.5 TP67.1 U21.12(4Y) U24.8 U27.8(DQ1) ; also on sheet 7
QSPI_MON1_FLASH_DQ2: J21.7 R412.2 TP68.1 U21.4(1Y) U24.9 U27.9(~{WP}/DQ2) ; also on sheet 7
QSPI_MON1_FLASH_DQ3: J21.6 R414.2 TP64.1 U21.7(2Y) U24.1 U27.1(DQ3/~{HOLD}) ; also on sheet 7
QSPI_MON2_QS_DISABLE: JP40.2 U21.15(~{OE}) U23.15(~{OE}) ; also on sheet 7
QSPI_MON2_QS_SEL: JP39.2 R422.2 U21.1(S) U23.1(S) ; also on sheet 7
QSPI_PCH_QS_SEL: R422.1 ; also on sheet 14
TCK: JP45.1 JP49.1 JP50.1 ; also on sheet 3
TDI: JP46.1 JP47.1 JP48.1 ; also on sheet 3
TDO: JP46.4 JP47.4 JP48.4 ; also on sheet 3
TMS: JP51.1 JP52.1 JP53.1 ; also on sheet 3
X3_CSSPIN: R330.2 U3.AA3(PB7A_CSSPIN)
X3_GSRN: C320.1 R590.2 TP82.1 U3.L1(PL16A_PCLKT4_0)
X3_I2C_SCL: R328.1 U3.H3(PL7D)
X3_I2C_SDA: R329.1 U3.H1(PL10B)
X3_LED_0: U3.T1(PL21B) ; also on sheet 25
X3_LED_1: U3.U1(PL25B) ; also on sheet 25
X3_LED_2: U3.R2(PL21A) ; also on sheet 25
X3_LED_3: U3.T2(PL25A) ; also on sheet 25
X3_LED_4: U3.R3(PL24A) ; also on sheet 25
X3_LED_5: U3.T3(PL26A) ; also on sheet 25
X3_LED_6: U3.R4(PL24B) ; also on sheet 25
X3_LED_7: U3.T4(PL26B) ; also on sheet 25
X3_LED_8: U3.R5(PL24C) ; also on sheet 25
X3_LED_9: U3.T5(PL26C) ; also on sheet 25
X3_OSC_EN: JP26.2 R336.2 U3.U3(PL27C) X5.1(~{SHDN})
X3_OSC_IN: R341.2 U3.U2(PL27A_PCLKT3_0)
X3_PB: C321.1 R592.2 TP83.1 U3.R1(PL19B)
X3_SN: R331.2 U3.AB21(PB46A_SN)
X3_TCK: J13.8 R445.1 R453.2 ; also on sheet 17
X3_TDI: J13.3 JP48.2 R440.2 ; also on sheet 17
X3_TDO: J13.2 JP46.3 R441.2 ; also on sheet 17
X3_TMS: J13.6 R439.2 R456.2 ; also on sheet 17
X3_UART_RXD: U3.N1(PL17B) ; also on sheet 3
X3_UART_TXD: U3.M1(PL17A) ; also on sheet 3
X3_X5_MPESTI-GPIO_0: Q5.G(GATE) R350.2 ; also on sheet 6
X3_X5_MPESTI-GPIO_1: Q7.G(GATE) R362.2 ; also on sheet 6
X3_X5_MPESTI-I_0: R359.1 U3.L7(PL13A)
X3_X5_MPESTI-I_1: R371.1 U3.K5(PL13B)
X3_X5_MPESTI-I_2: R378.1 U3.K4(PL13C)
X3_X5_MPESTI-T_0: R360.2 ; also on sheet 6
X3_X5_MPESTI-T_1: R372.2 ; also on sheet 6
X3_X5_MPESTI-T_2: R379.2 R380.1 ; also on sheet 6
X5_FLASHA_RSTN: R555.1 ; also on sheet 7
X5_FLASHB_RSTN: R556.1 ; also on sheet 7
X5_FLASHC_RSTN: R397.1 ; also on sheet 7
X5_FLASHD_RSTN: R398.1 ; also on sheet 7
X5_TCK: J14.8 R446.1 R451.2 ; also on sheet 4
X5_TDI: J14.3 JP46.2 R443.2 ; also on sheet 4
X5_TDO: J14.2 JP47.3 R444.2 ; also on sheet 4
X5_TMS: J14.6 R442.2 R454.2 ; also on sheet 4
X5_X3_GPIO_0: U3.D1(PL5A) ; also on sheet 8
X5_X3_GPIO_1: U3.E1(PL6A) ; also on sheet 8
X5_X3_GPIO_2: U3.D2(PL4B_L_GPLLC_IN) ; also on sheet 8
X5_X3_GPIO_3: U3.E2(PL5B) ; also on sheet 8
X5_X3_GPIO_4: U3.D3(PL2A) ; also on sheet 8
X5_X3_GPIO_5: U3.E3(PL5C) ; also on sheet 8
X5_X3_GPIO_6: U3.D4(PL2B) ; also on sheet 8
X5_X3_GPIO_7: U3.E4(PL3A_L_GPLLT_FB) ; also on sheet 8
X5_X3_GPIO_8: U3.F1(PL6B) ; also on sheet 8
X5_X3_GPIO_9: U3.F4(PL5D) ; also on sheet 8
X5_X3_I3C_SCL: R328.2 U3.G2(PL7A_PCLKT5_0) ; also on sheet 8 27
X5_X3_I3C_SDA: R329.2 U3.H2(PL10A) ; also on sheet 8 27
X5_X3_LTPI_TXCLK_N: R334.2 U3.AA12(PB29B_PCLKC2_1) ; also on sheet 6
X5_X3_LTPI_TXCLK_P: R332.1 U3.AB12(PB29A_PCLKT2_1) ; also on sheet 6
X5_X3_LTPI_TXD_N: R339.2 U3.AA13(PB30B) ; also on sheet 6
X5_X3_LTPI_TXD_P: R337.1 U3.AB13(PB30A) ; also on sheet 6
X5_X3_MPESTI-GPIO_0: Q4.G(GATE) R349.2 U3.K3(PL13D)
X5_X3_MPESTI-GPIO_1: Q6.G(GATE) R361.2 U3.K1(PL14B)
X5_X3_MPESTI-I_0: R357.1 ; also on sheet 6
X5_X3_MPESTI-I_1: R369.1 ; also on sheet 6
X5_X3_MPESTI-I_2: R375.1 ; also on sheet 6
X5_X3_MPESTI-T_0: R358.2 U3.K2(PL14A)
X5_X3_MPESTI-T_1: R370.2 U3.L6(PL14C)
X5_X3_MPESTI-T_2: R376.2 R377.1 U3.L5(PL14D)
X5_X3_SGPIO_0: U3.G1(PL7B_PCLKC5_0) ; also on sheet 8
X5_X3_SGPIO_1: U3.J3(PL11D) ; also on sheet 8
X5_X3_SGPIO_2: U3.J2(PL12A) ; also on sheet 8
X5_X3_SGPIO_3: U3.J1(PL12B) ; also on sheet 8
XO3_SCM_RXCLK_N: U3.AB10(PB22B_PCLKC2_0) ; also on sheet 26
XO3_SCM_RXCLK_P: U3.AA10(PB22A_PCLKT2_0) ; also on sheet 26
XO3_SCM_RXD_N: U3.AB11(PB24B) ; also on sheet 26
XO3_SCM_RXD_P: U3.AA11(PB24A) ; also on sheet 26
XO3D_CORE: C216.1 C217.1 C218.1 C219.1 C220.1 C221.1 C222.1 C223.1 C224.1 C225.1 C226.1 C227.1 C228.1 C229.1 C230.1 R342.2 TP46.1 U3.K10(VCC1) U3.K11(VCC2) U3.K12(VCC3) U3.K13(VCC4) U3.L11(VCC5) U3.L12(VCC6) U3.M11(VCC7) U3.M12(VCC8) U3.N10(VCC9) U3.N11(VCC10) U3.N12(VCC11) U3.N13(VCC12)
XO3D_VCCIO_0: C261.1 C262.1 C263.1 C264.1 C265.1 C266.1 C267.1 C268.1 C269.1 C270.1 C271.1 C272.1 R343.2 TP47.1 U3.C7(VCCIO0_1) U3.C12(VCCIO0_2) U3.C16(VCCIO0_3) U3.G10(VCCIO0_4) U3.G13(VCCIO0_5) U3.H9(VCCIO0_6) U3.H11(VCCIO0_7) U3.H12(VCCIO0_8) U3.H14(VCCIO0_9)
XO3D_VCCIO_1: C237.1 C238.1 C239.1 C240.1 C241.1 C242.1 C243.1 C244.1 C245.1 C246.1 C247.1 C248.1 R346.2 TP50.1 U3.F20(VCCIO1_1) U3.J15(VCCIO1_2) U3.K15(VCCIO1_3) U3.L15(VCCIO1_4) U3.M15(VCCIO1_5) U3.M18(VCCIO1_6) U3.N15(VCCIO1_7) U3.P15(VCCIO1_8) U3.V20(VCCIO1_9)
XO3D_VCCIO_2: C273.1 C274.1 C275.1 C276.1 C277.1 C278.1 C279.1 C280.1 C281.1 C282.1 C283.1 C284.1 R344.2 TP48.1 U3.R9(VCCIO2_1) U3.R10(VCCIO2_2) U3.R11(VCCIO2_3) U3.R12(VCCIO2_4) U3.R13(VCCIO2_5) U3.R14(VCCIO2_6) U3.W7(VCCIO2_7) U3.W11(VCCIO2_8) U3.W16(VCCIO2_9)
XO3D_VCCIO_3: C255.1 C256.1 C257.1 C258.1 C259.1 C260.1 R347.2 TP51.1 U3.N8(VCCIO3_1) U3.P8(VCCIO3_2) U3.V3(VCCIO3_3)
XO3D_VCCIO_4: C249.1 C250.1 C251.1 C252.1 C253.1 C254.1 R345.2 TP49.1 U3.L8(VCCIO4_1) U3.M3(VCCIO4_3) U3.M8(VCCIO4_2)
XO3D_VCCIO_5: C231.1 C232.1 C233.1 C234.1 C235.1 C236.1 R348.2 TP52.1 U3.F3(VCCIO5_1) U3.J8(VCCIO5_2) U3.K8(VCCIO5_3)
N17915494: JP45.2 R451.1
N17915507: JP49.2 R452.1
N17915521: JP51.2 R454.1
N17915528: JP52.2 R455.1
N18416877: Q4.D(DRAIN) R351.1 R355.1
N18416915: JP27.2 R355.2 R358.1
N18417060: JP27.1 R352.2 R357.2
N18417665: Q6.D(DRAIN) R363.1 R367.1
N18417703: JP29.2 R367.2 R370.1
N18417715: JP29.1 R365.2 R369.2
N18417905: JP31.2 R376.1
N18417937: JP31.1 R373.2 R375.2
N18418144: Q5.D(DRAIN) R354.1 R356.1
N18418182: JP28.2 R356.2 R360.1
N18418194: JP28.1 R353.2 R359.2
N18418257: Q7.D(DRAIN) R364.1 R368.1
N18418295: JP30.2 R368.2 R372.1
N18418307: JP30.1 R366.2 R371.2
N18418357: JP32.1 R374.2 R378.2
N18418389: JP32.2 R379.1
N18488359: R341.1 X5.3(OUT)
N18696225: JP50.2 R453.1
N18696253: JP53.2 R456.1
N19216815: JP33.1 R381.1
N19269480: JP39.1 R411.2
N19275179: JP40.1 R420.2
N19787391: C213.1 R332.2 R333.2 R334.1 R335.1
N19787469: C215.1 R337.2 R338.2 R339.1 R340.1
N20305116: R589.2 R590.1 SW16.2 SW16.4
N20305475: R591.2 R592.1 SW17.2 SW17.4
N20319038: JP33.3 R384.1
N20320677: JP34.1 R392.2
N20320690: JP34.3 R587.1
N20322030: JP39.3 R425.1
N20322952: JP40.3 R588.1

Not connected (* = marked no-connect by the designer): J13 4* 5*; J14 4* 5*; J15 4* 5*; J20 1* 11* 12*; J21 1* 11* 12*; U3 AA1(PL29B) AA2(PB5A) AA4(PB8A) AA5(PB10A) AA6(PB11A) AA7(PB13A) AA8(PB18A) AA9(PB19A) AA14(PB33B) AA15(PB35B) AA16(PB38B) AA17(PB40B) AA18(PB41B) AA19(PB43B) AA20(PB44B) AA21(PB46B_SI/SISPI) AB2(PB5B) AB3(PB7B) AB4(PB8B) AB5(PB10B) AB6(PB11B) AB7(PB13B) AB8(PB18B) AB9(PB19B) AB14(PB33A) AB15(PB35A) AB16(PB38A) AB17(PB40A) AB18(PB41A) AB19(PB43A) AB20(PB44A) C1(PL4A_L_GPLLT_IN) F5(PL3B_L_GPLLC_FB) F6(PL2C) G3(PL6C) G4(PL6D) G5(PL4C) G6(PL3C) G7(PL2D) H4(PL7C) H5(PL11A) H6(PL4D) H7(PL3D) J4(PL11C) J5(PL11B) J6(PL10D) J7(PL10C) K6(PL12D) K7(PL12C) L3(PL16C) L4(PL16D) M2(PL16B_PCLKC4_0) M5(PL17D) M6(PL17C) M7(PL19D) N2(PL18A) N3(PL18C) N4(PL18D) N5(PL20B) N6(PL20C) N7(PL20D) P1(PL18B) P2(PL19A) P3(PL19C) P4(PL20A) P5(PL21C) P6(PL21D) P7(PL24D) R6(PL25C) R7(PL25D) T6(PL26D) T7(PL30D) T8(PB8D) T9(PB16A_MCLK/CCLK) T10(PB19C) T11(PB22C) T12(PB27B) T13(PB32A) T14(PB32B) T15(PB43C) T16(PB46D) U4(PL27D) U5(PL28D) U6(PB5D) U7(PB8C) U8(PB13D) U9(PB16B_SO/SPISO) U10(PB19D) U11(PB22D) U12(PB27C) U13(PB29D) U14(PB32C) U15(PB38D) U16(PB43D) V1(PL27B_PCLKC3_0) V4(PL28C) V5(PL30C) V6(PB5C) V7(PB11D) V8(PB13C) V9(PB16C) V10(PB21A) V11(PB24C) V12(PB27D) V13(PB29C) V14(PB32D) V15(PB38C) V16(PB40D) V17(PB46C) W1(PL28A) W2(PL28B) W3(PL29C) W4(PL30B) W5(PB7D) W6(PB11C) W8(PB16D) W9(PB18D) W10(PB21B) W13(PB30D) W14(PB33D) W15(PB35D) W17(PB41D) W18(PB44D) Y1(PL29A) Y2(PL29D) Y3(PL30A) Y4(PB7C) Y5(PB10C) Y6(PB10D) Y8(PB18C) Y9(PB21C) Y10(PB21D) Y11(PB24D) Y12(PB27A) Y13(PB30C) Y14(PB33C) Y15(PB35C) Y17(PB40C) Y18(PB41C) Y19(PB44C); U15 12(4Y)*; U16 4* 5* 6* 11* 12* 13* 14*; U19 4(DNU1)* 5(DNU2)* 6(DNU3)* 11(DNU4)* 12(DNU5)* 13(DNU6)* 14(DNU7)*; U23 12(4Y)*; U24 4* 5* 6* 11* 12* 13* 14*; U27 4(DNU1)* 5(DNU2)* 6(DNU3)* 11(DNU4)* 12(DNU5)* 13(DNU6)* 14(DNU7)*

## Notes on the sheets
sheet 19
- 3.3V
- LEDs Signal Map
- 1.8V
- U3
  Pin
- Signal
- LED
- T1
- X3_LED_0
- D55
- U1
- X3_LED_1
- D56
- R2
- X3_LED_2
- D57
- T2
- X3_LED_3
- D58
- R3
- X3_LED_4
- D59
- 3.3V
- T3
- X3_LED_5
- D60
- R4
- X3_LED_6
- D61
- T4
- X3_LED_7
- D62
- R5
- X3_LED_8
- D63
- T5
- X3_LED_9
- D64
- 3.3V
- FPGA GSRN
- 50ohm trace
- GP BUTTON
- 2.5 x 2.0 mm 4-SMD
- PLACE X5 CLOSE TO U3
- OSCILLATOR 25MHZ
sheet 21
- XO5D TO XO3D
- XO3D TO XO5D
sheet 22
- From PFR QSPI Mon#0
- DNP
- To PFR QSPI Mon#0
  and Flash C, D
- From CPNX MSPI/BMC QSPI
- From PFR QSPI Mon#0
- CS SELECTION JUMPER
- DNP
- To PFR QSPI Mon#0
  and Flash C, D
- From CPNX MSPI/BMC QSPI
- Flash C
- DQ3
- SCLK
- VCC
- DQ0
- RST#
- NC
- NC
- NC
- NC
- NC
- NC
- NC
- CS#
- VSS
- DQ1
- DQ2
- DEDIPROG HEADER
- Flash D
sheet 23
- From PFR QSPI Mon#2
- To PFR QSPI Mon#2
  and Flash A, B
- DNP
- From PCH MUX OE
- CS SELECTION JUMPER
- From CPNX MSPI/PCH QSPI
- From PFR QSPI Mon#2
- DNP
- To PFR QSPI Mon#2
  and Flash A, B
- From CPNX MSPI/PCH QSPI
- Flash A
- DQ3
- SCLK
- VCC
- DQ0
- RST#
- NC
- NC
- NC
- NC
- NC
- NC
- NC
- CS#
- VSS
- DEDIPROG HEADER
- DQ1
- DQ2
- Flash B
sheet 24
- DNP
- DNP
- DNP
